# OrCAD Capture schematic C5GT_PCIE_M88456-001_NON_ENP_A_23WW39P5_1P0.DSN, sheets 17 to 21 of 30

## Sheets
17 10/100/1000 Ethernet PHY: size B
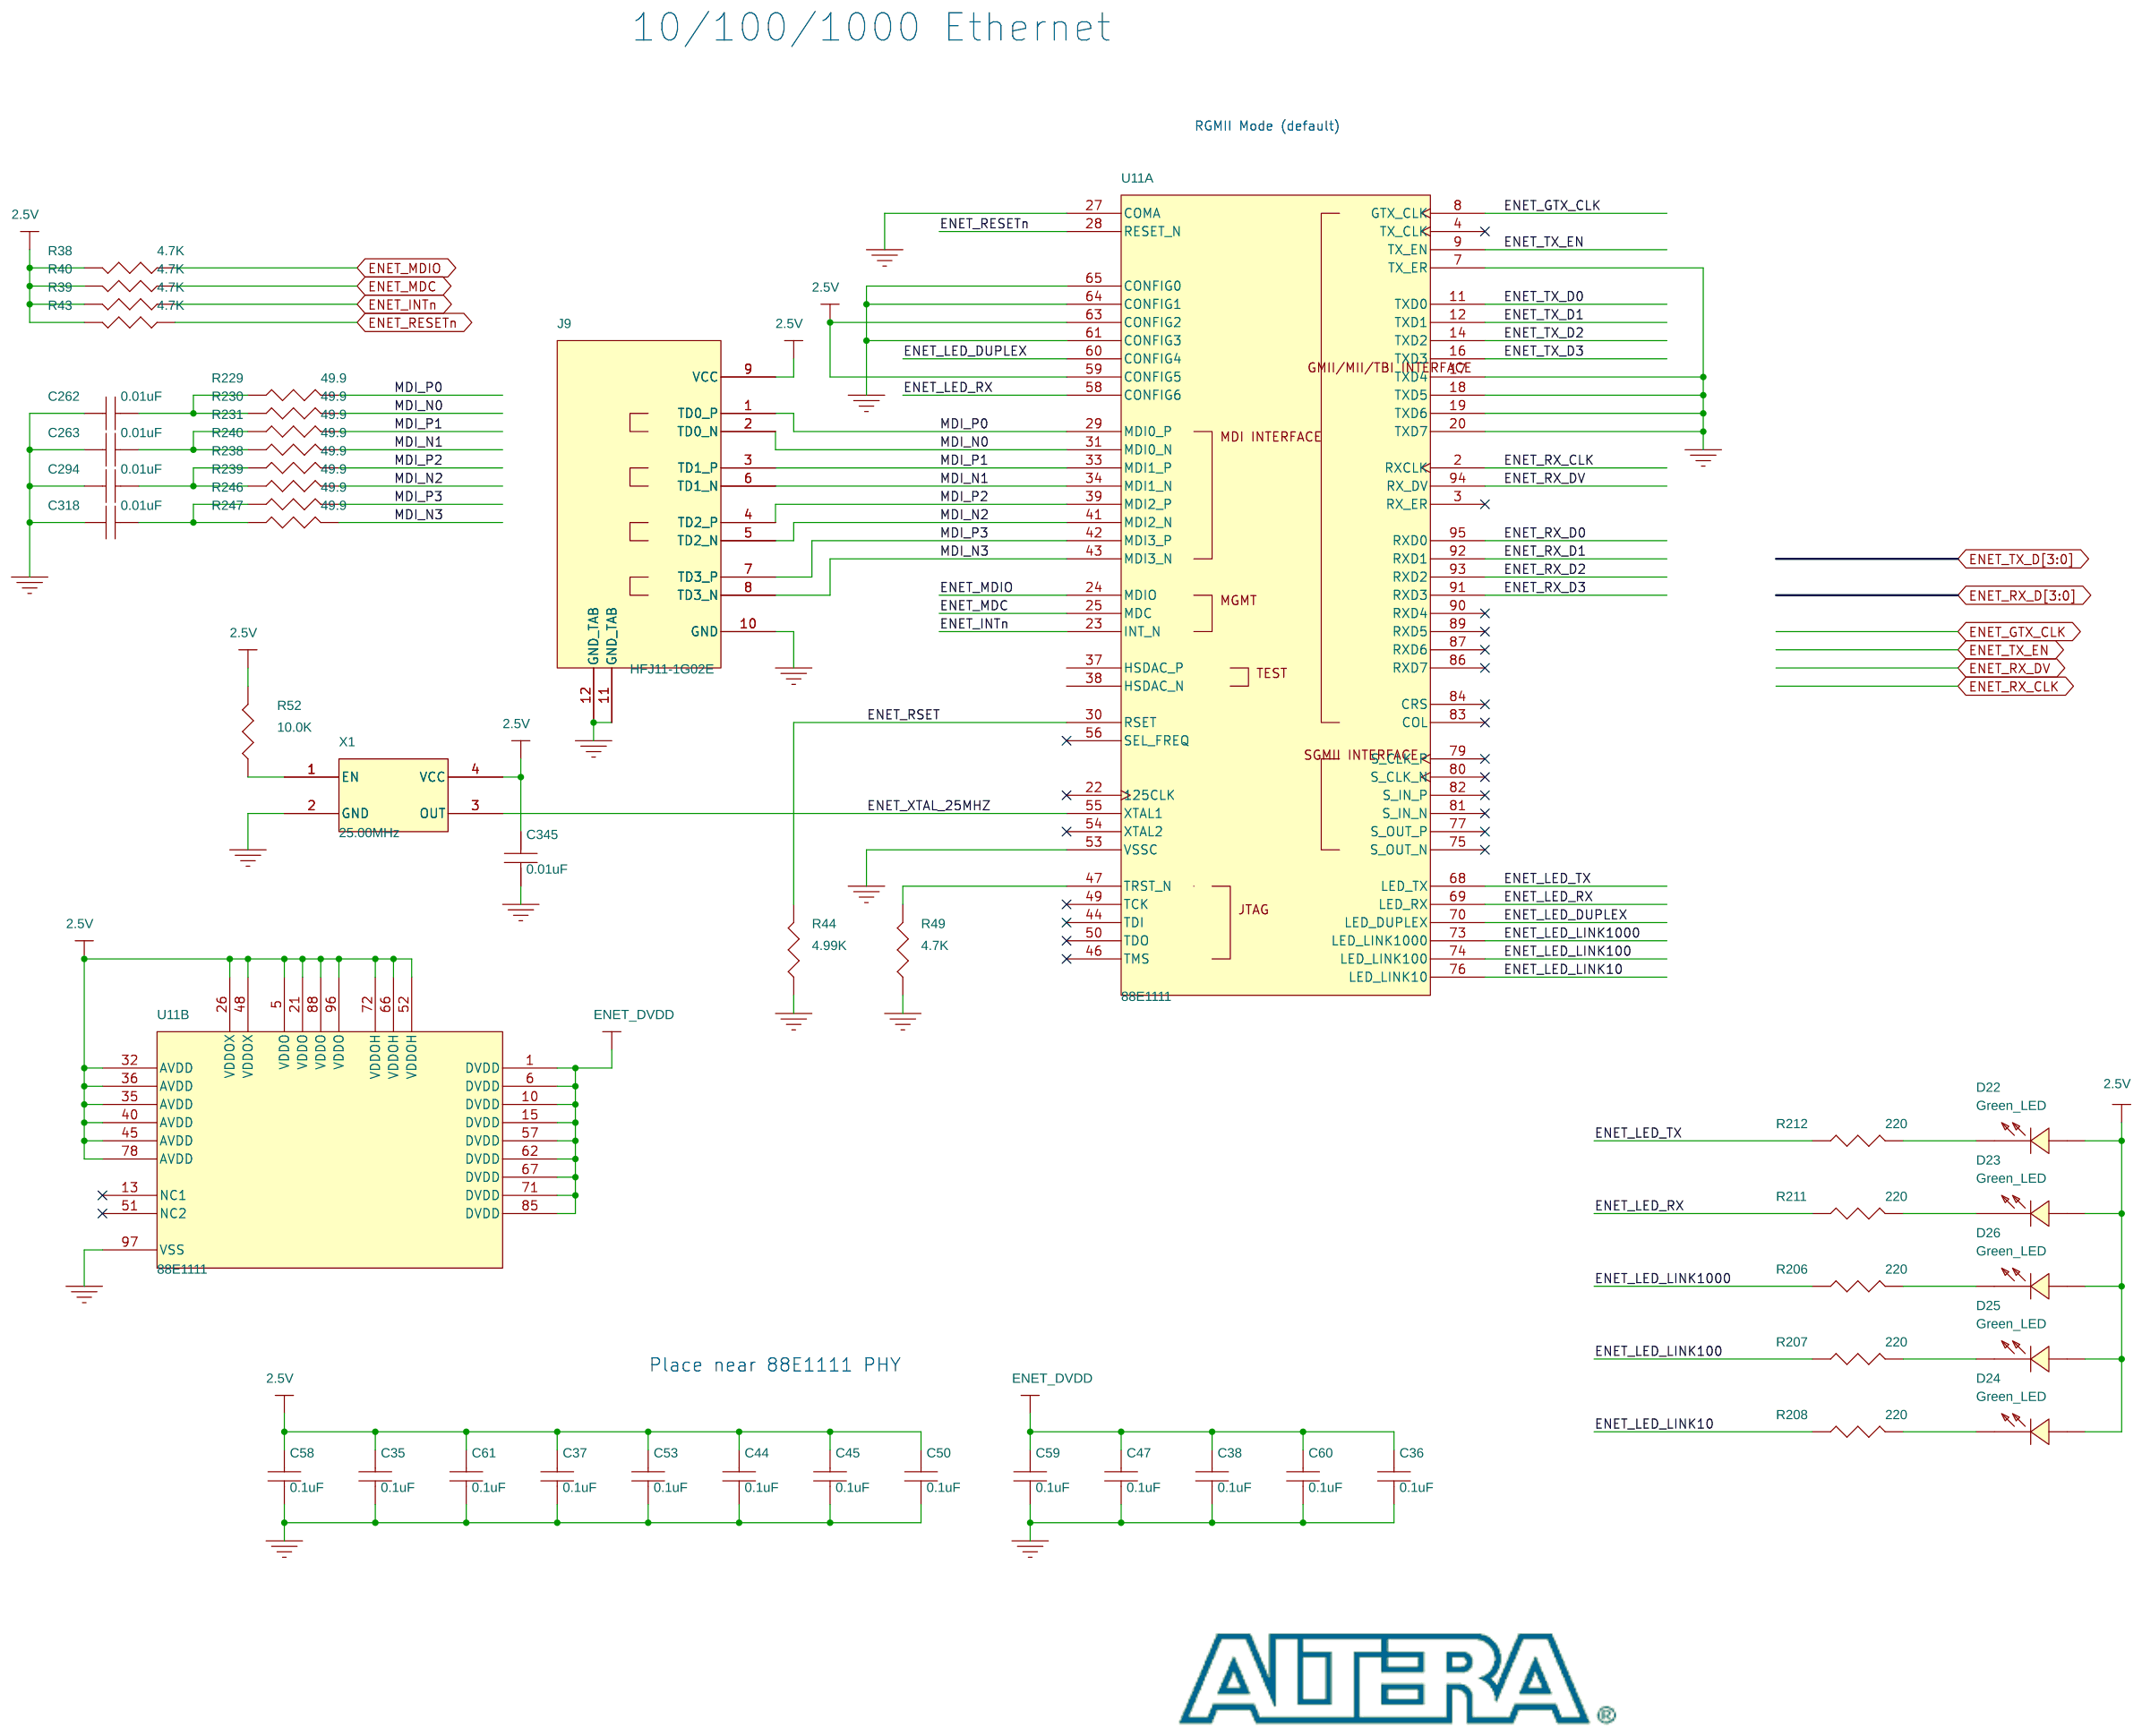
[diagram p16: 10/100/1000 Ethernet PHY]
18 HSMC Port A & Port B: size B
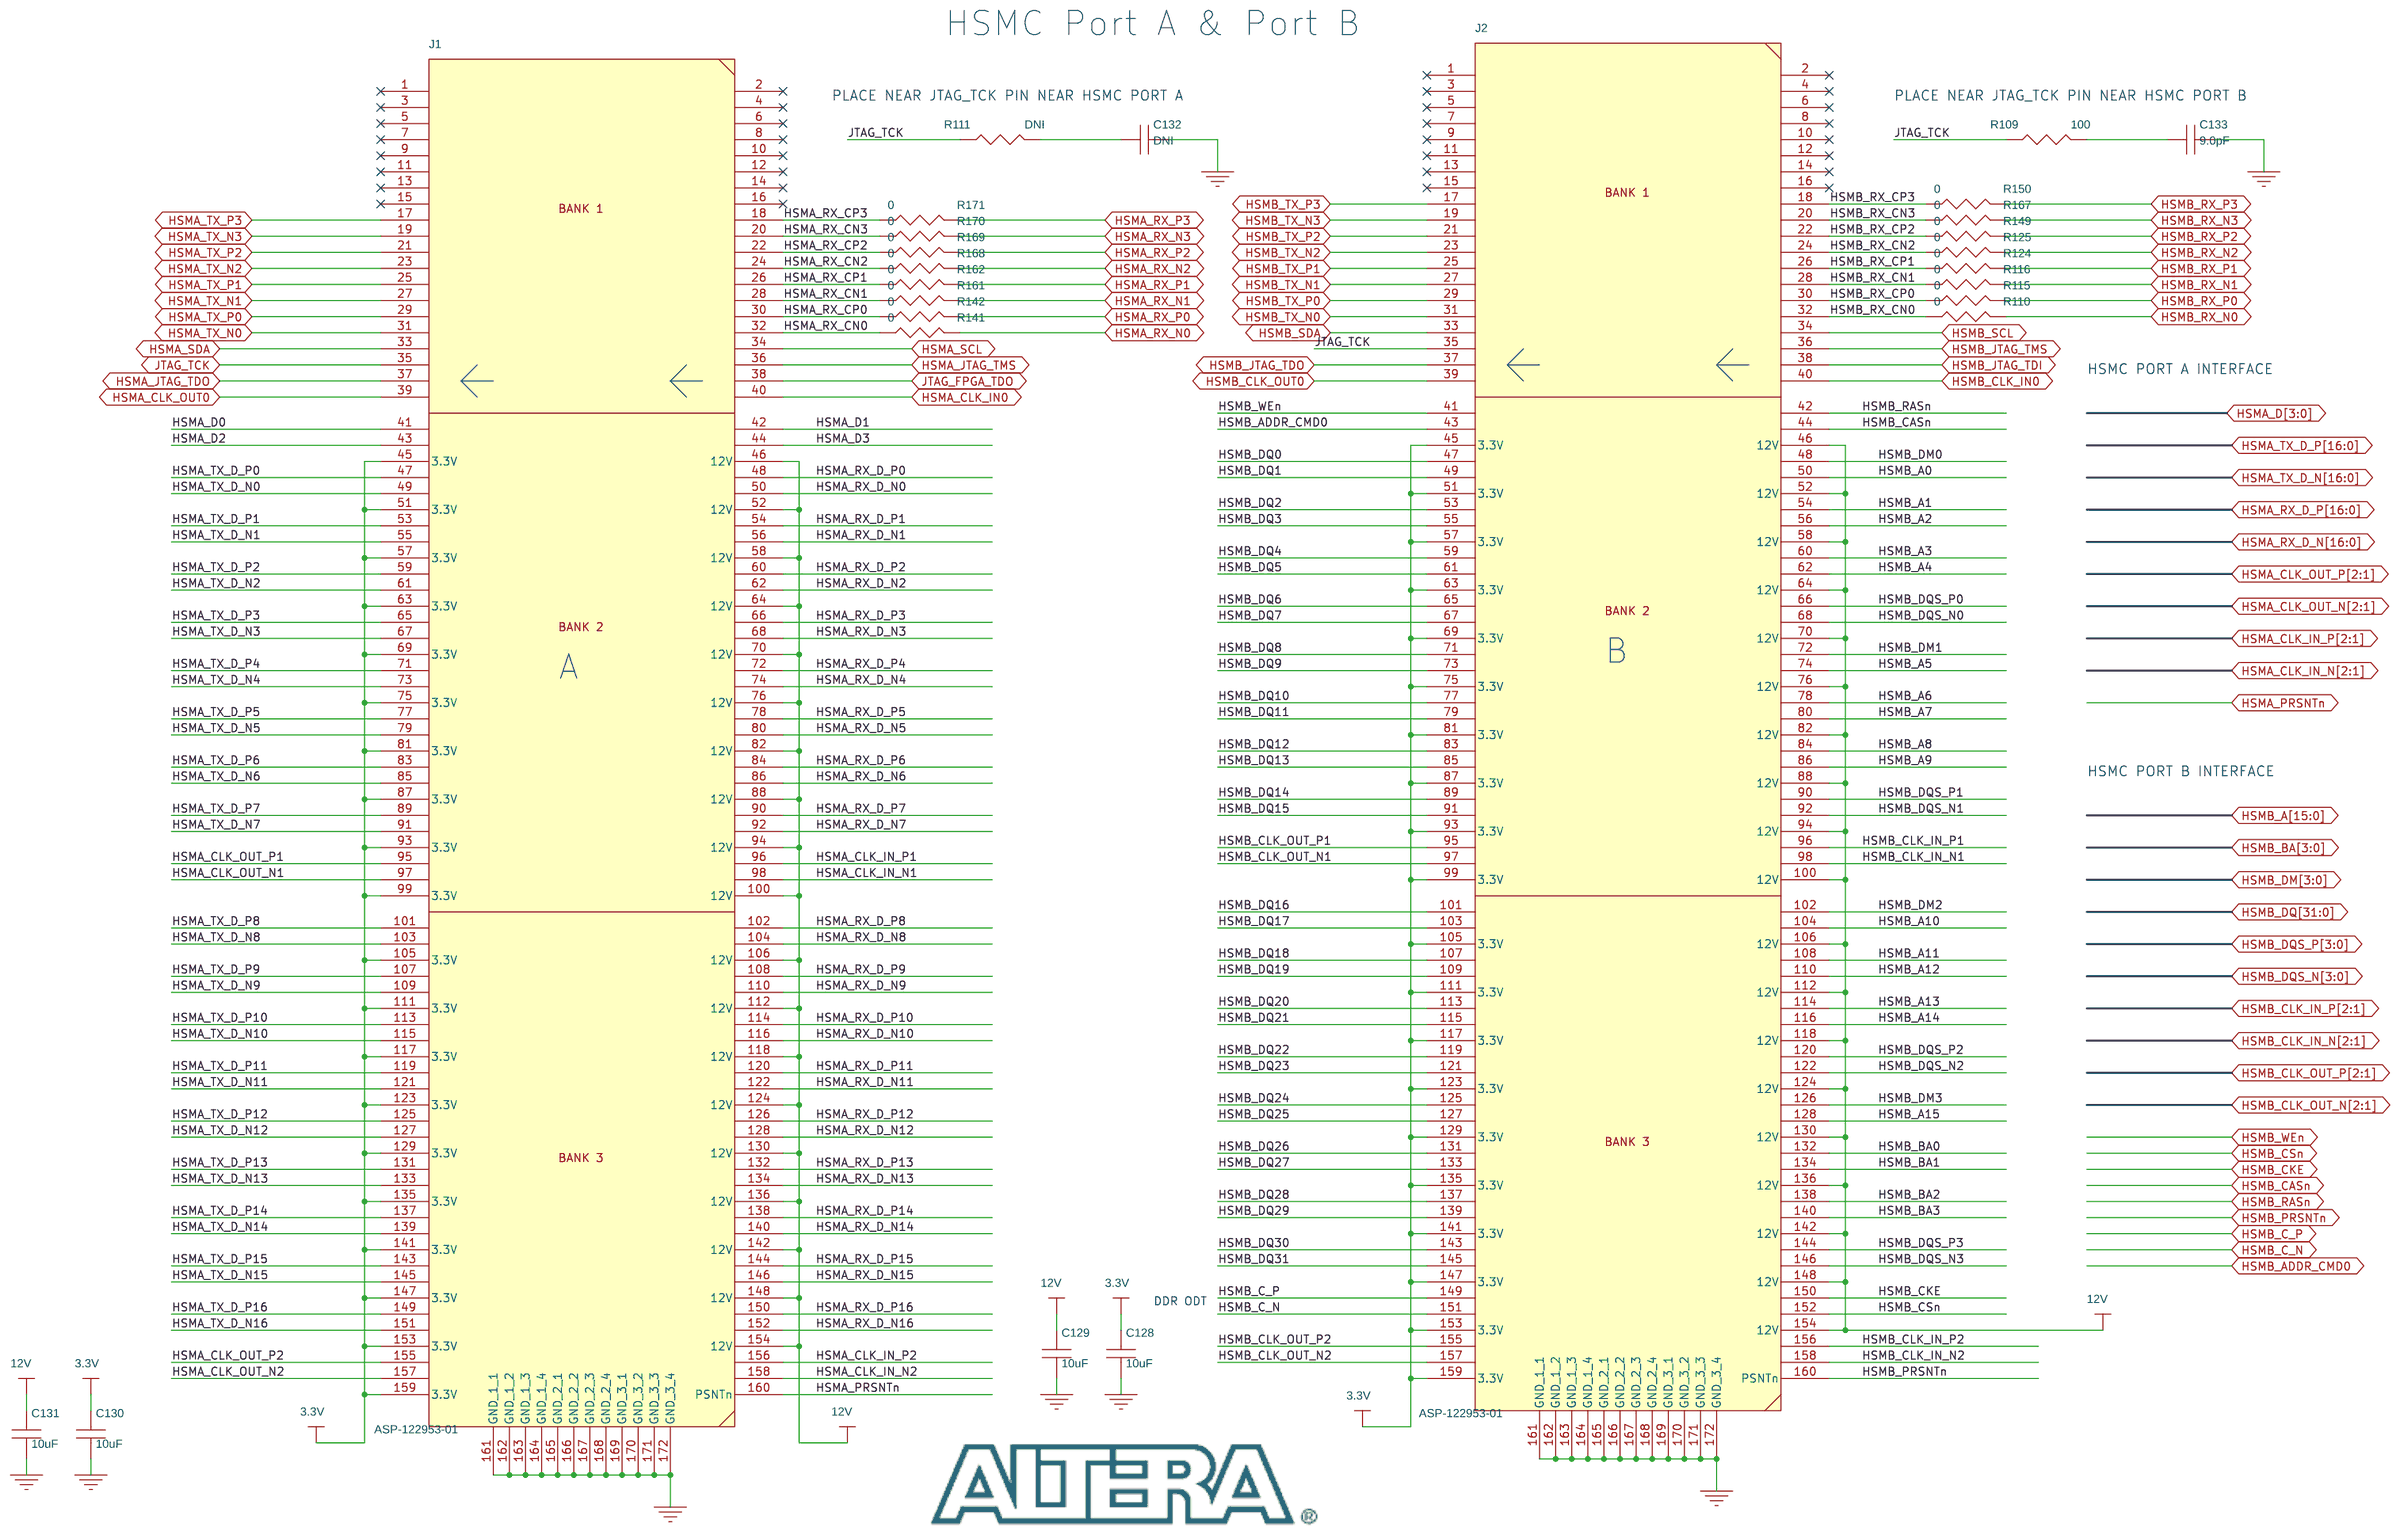
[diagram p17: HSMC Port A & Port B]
19 On-Board USB Blaster II: size B
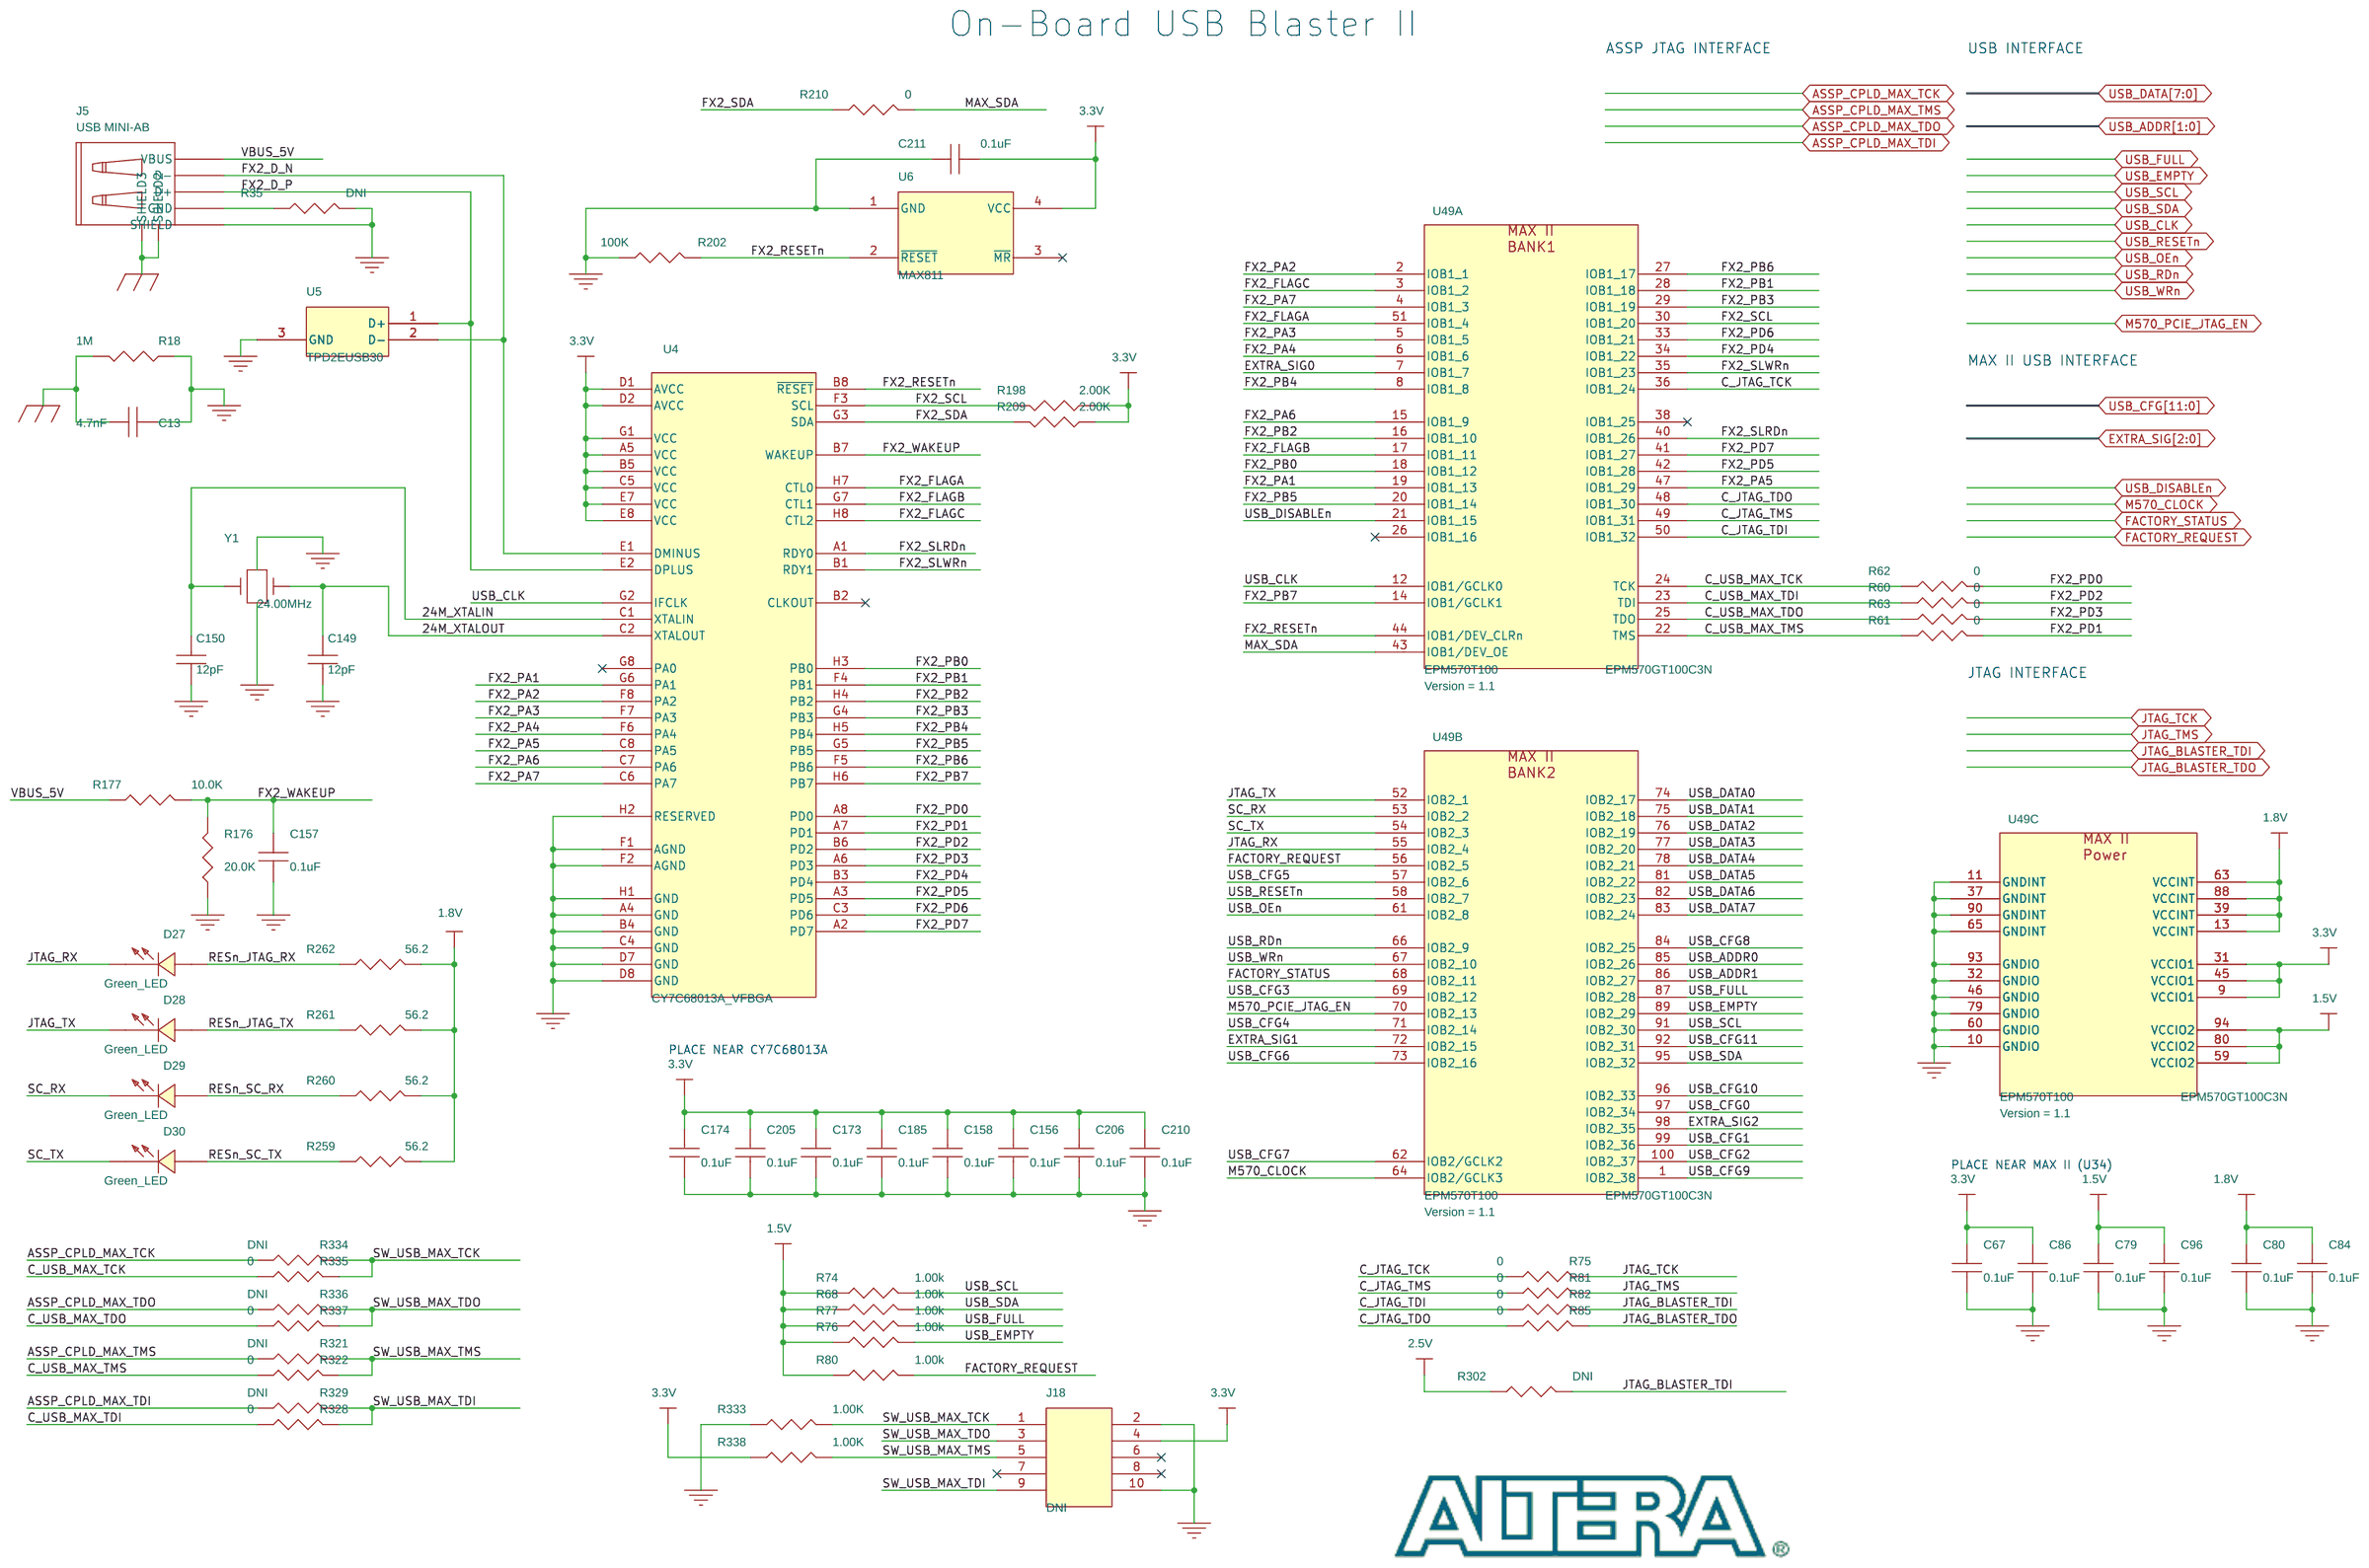
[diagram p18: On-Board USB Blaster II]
20 User IO: size B
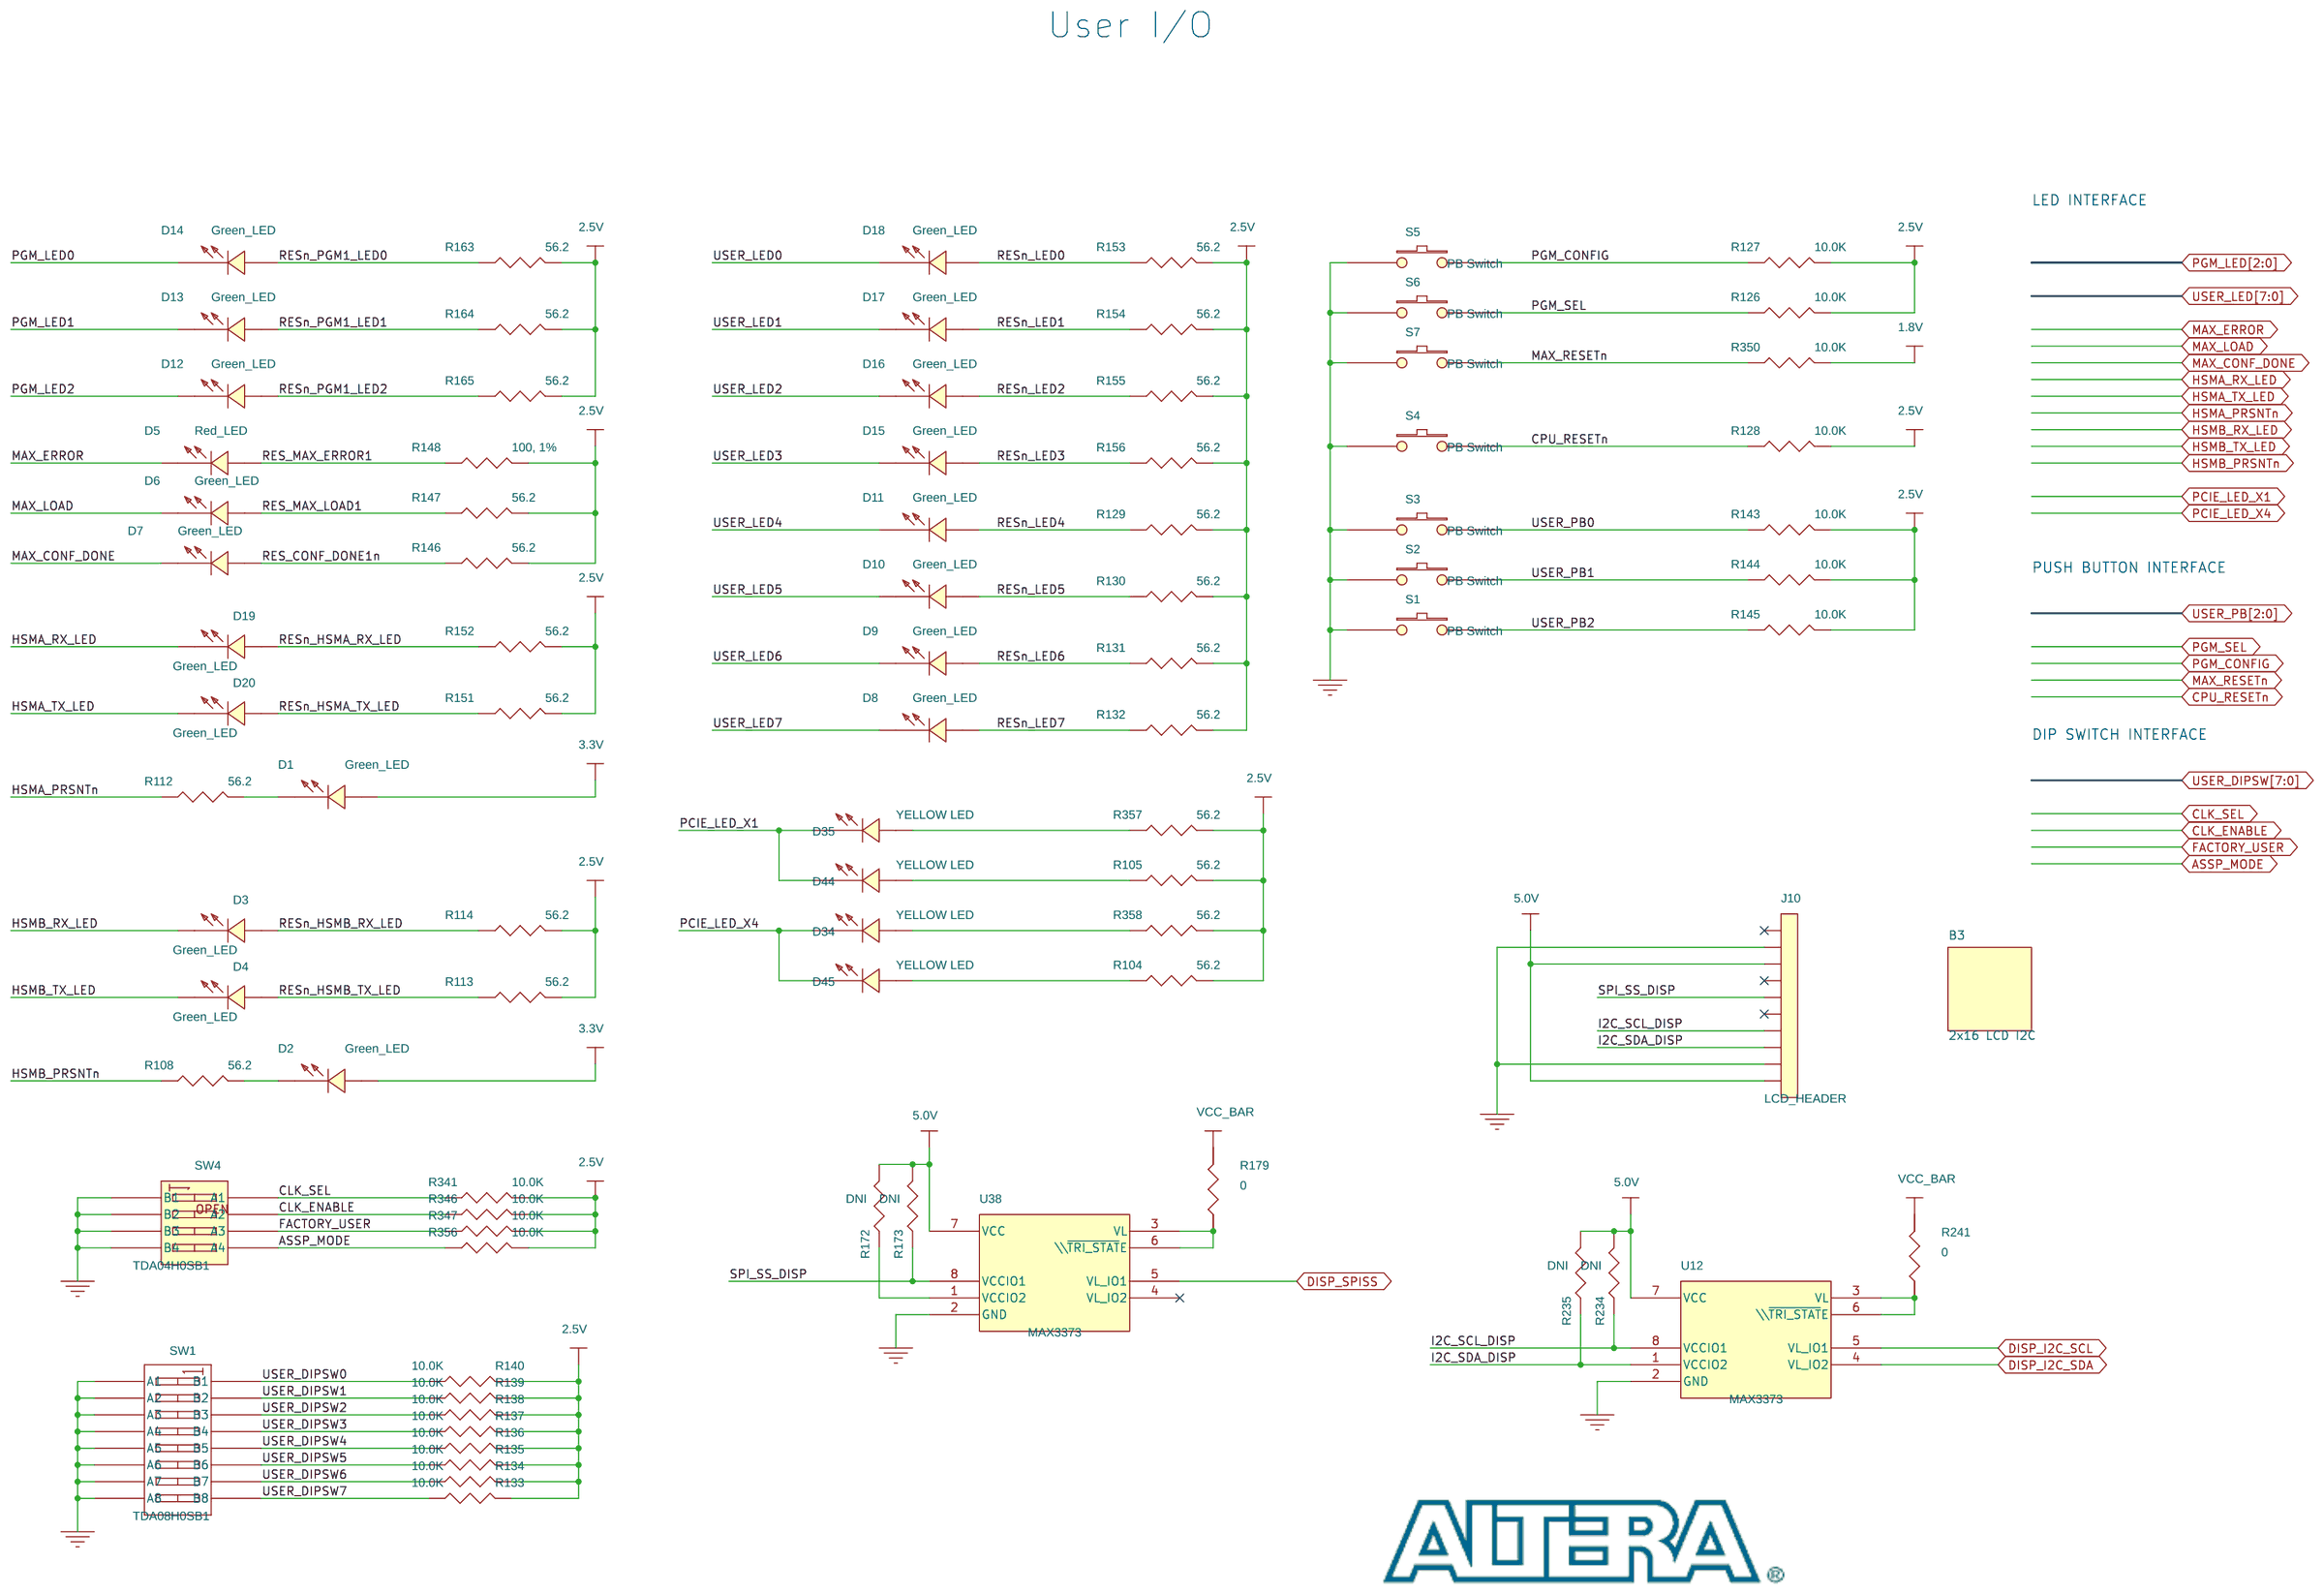
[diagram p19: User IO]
21 ASSP CPLD: size B
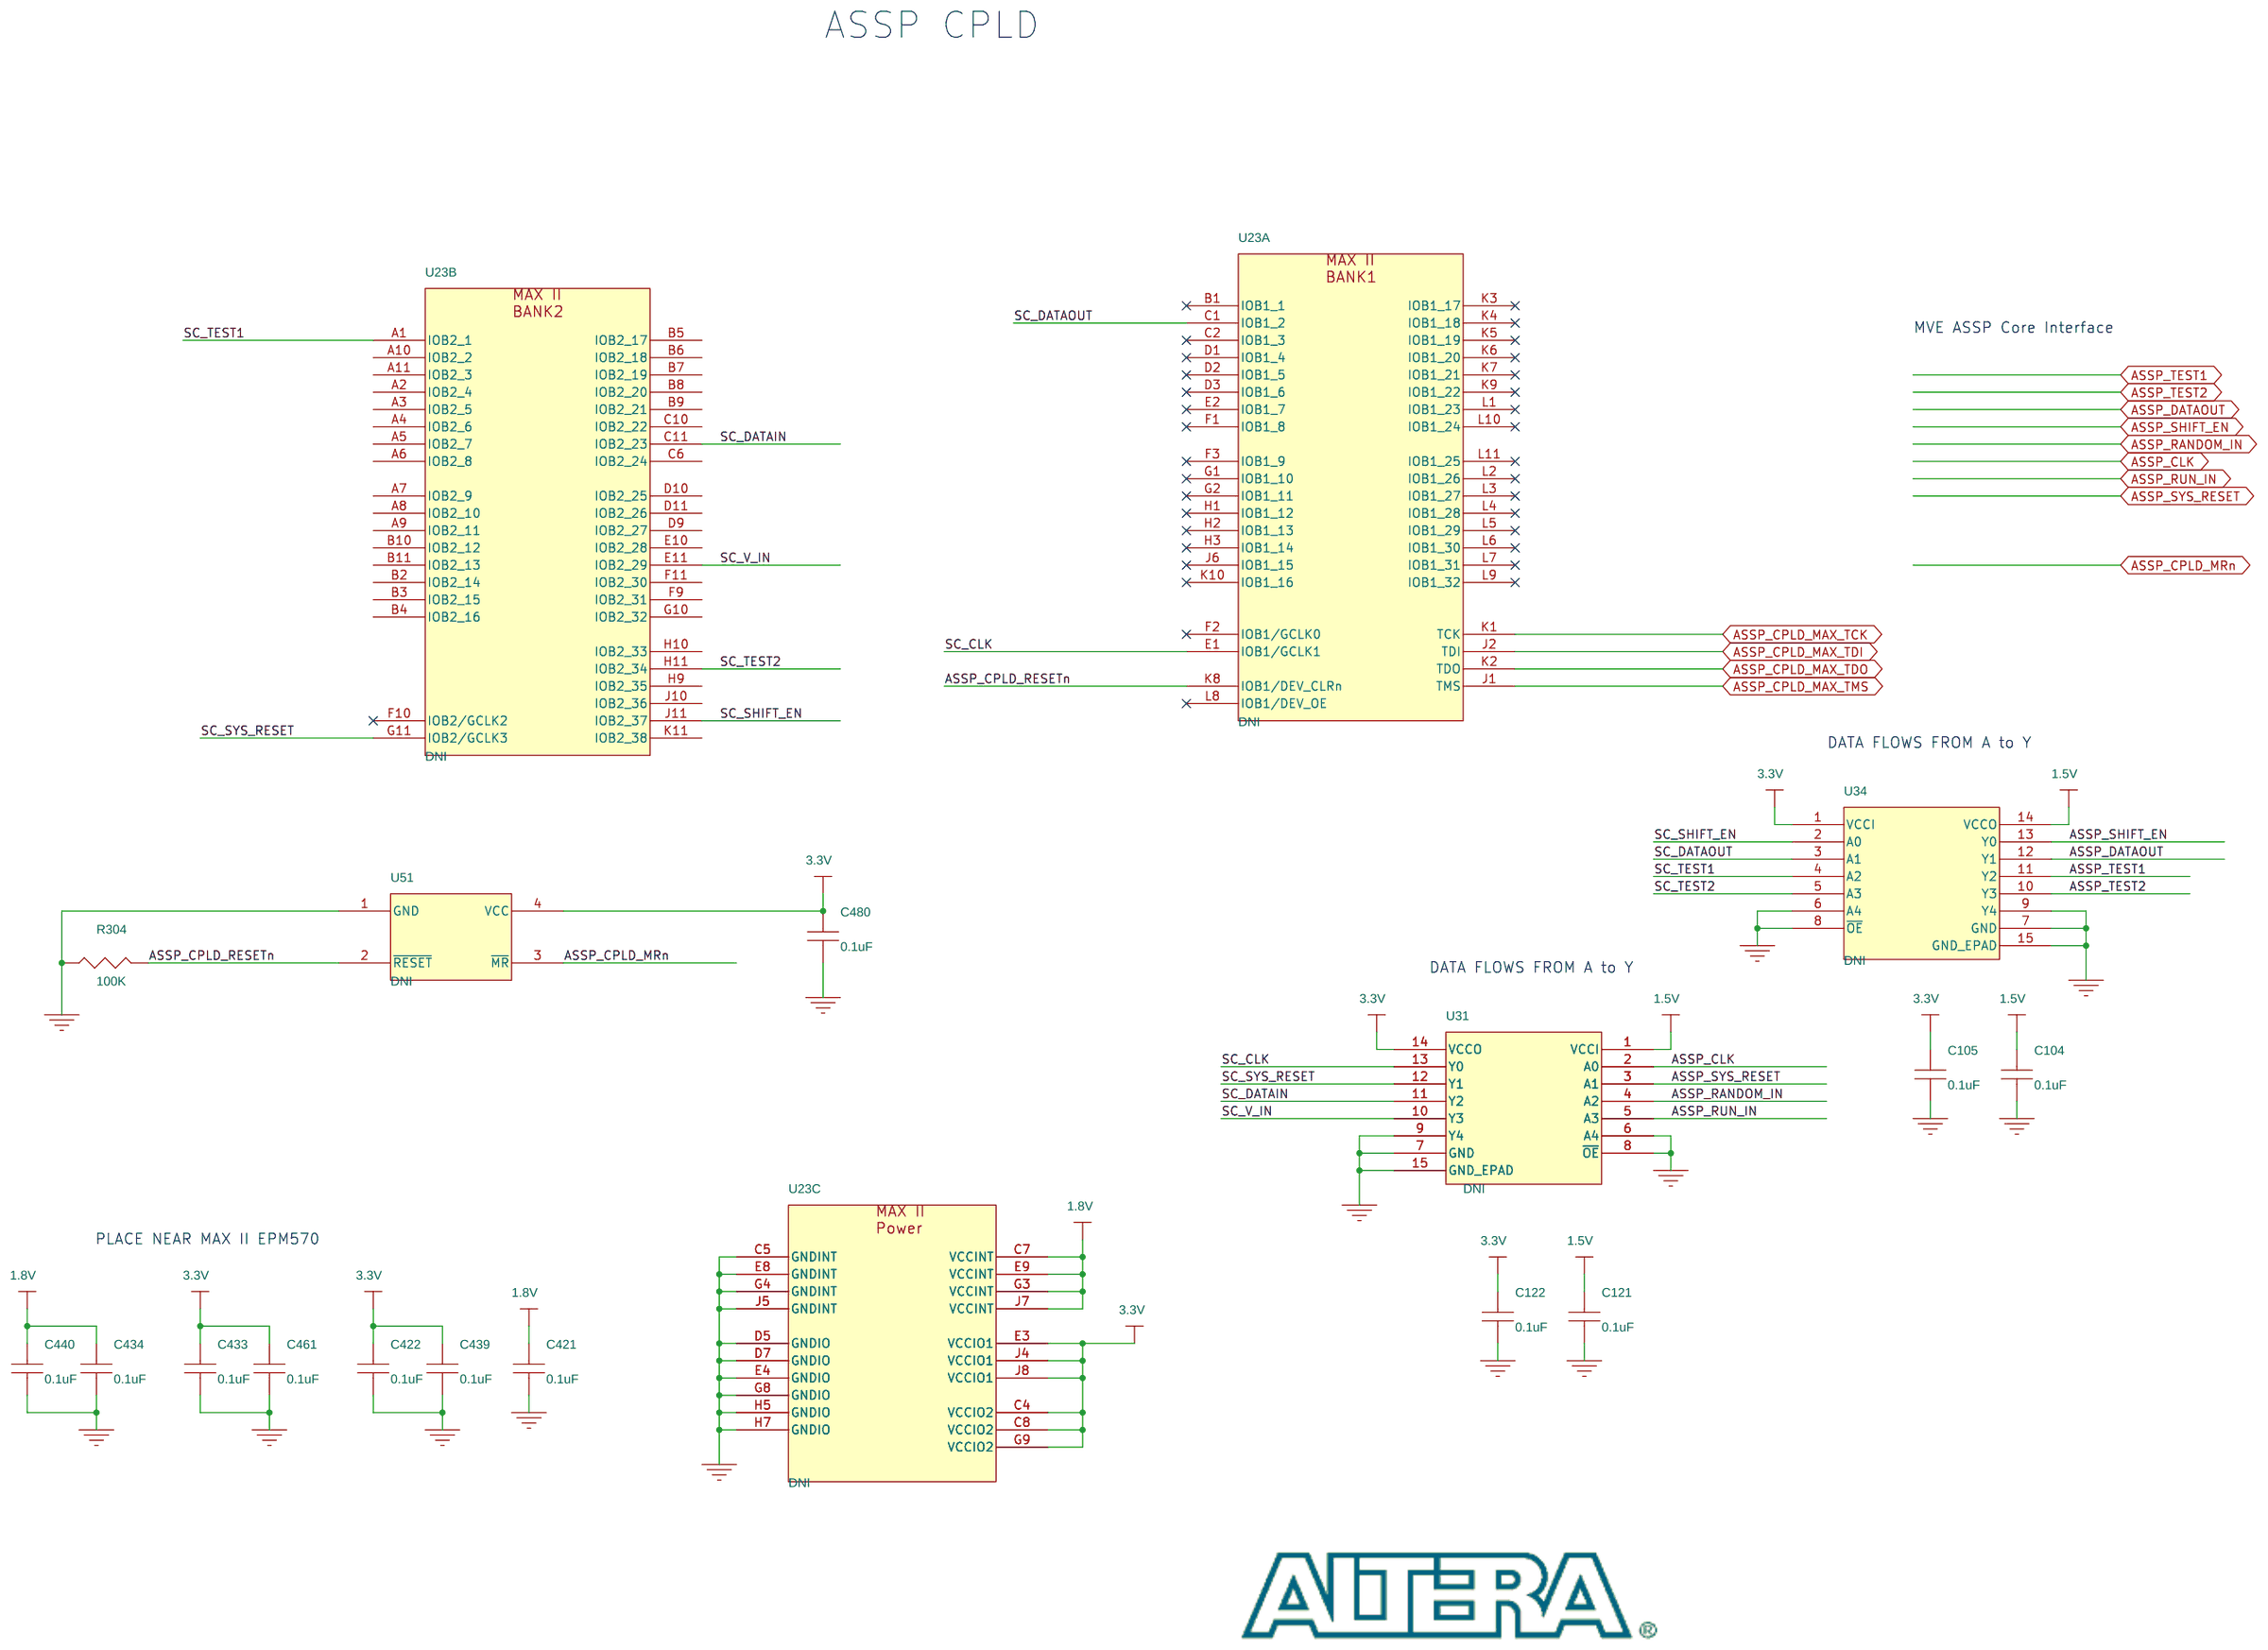
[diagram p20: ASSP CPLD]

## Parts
sheet 10/100/1000 Ethernet PHY
C35  0.1uF  [0402]
C36  0.1uF  [0402]
C37  0.1uF  [0402]
C38  0.1uF  [0402]
C44  0.1uF  [0402]
C45  0.1uF  [0402]
C47  0.1uF  [0402]
C50  0.1uF  [0402]
C53  0.1uF  [0402]
C58  0.1uF  [0402]
C59  0.1uF  [0402]
C60  0.1uF  [0402]
C61  0.1uF  [0402]
C262  0.01uF  [0402]
C263  0.01uF  [0402]
C294  0.01uF  [0402]
C318  0.01uF  [0402]
C345  0.01uF  [0402]
D22  Green_LED  [LUMEX_LED0805]
D23  Green_LED  [LUMEX_LED0805]
D24  Green_LED  [LUMEX_LED0805]
D25  Green_LED  [LUMEX_LED0805]
D26  Green_LED  [LUMEX_LED0805]
J9  HFJ11-1G02E  [rj45]
R38  4.7K  [0402]
R39  4.7K  [0402]
R40  4.7K  [0402]
R43  4.7K  [0402]
R44  4.99K  [0402]
R49  4.7K  [0402]
R52  10.0K  [0402]
R206  220  [0402]
R207  220  [0402]
R208  220  [0402]
R211  220  [0402]
R212  220  [0402]
R229  49.9  [0402]
R230  49.9  [0402]
R231  49.9  [0402]
R238  49.9  [0402]
R239  49.9  [0402]
R240  49.9  [0402]
R246  49.9  [0402]
R247  49.9  [0402]
U11  88E1111  [BCC96]  (sections A,B)
X1  25.00MHz  [XTAL_SG310]
sheet ASSP CPLD
C104  0.1uF  [0402]
C105  0.1uF  [0402]
C121  0.1uF  [0402]
C122  0.1uF  [0402]
C421  0.1uF  [0402]
C422  0.1uF  [0402]
C433  0.1uF  [0402]
C434  0.1uF  [0402]
C439  0.1uF  [0402]
C440  0.1uF  [0402]
C461  0.1uF  [0402]
C480  0.1uF  [0402]
R304  100K  [0402]
U23  DNI  [M100]  (sections A,B,C)
U31  DNI  [DQFN14]
U34  DNI  [DQFN14]
U51  DNI  [SOT-143]
sheet HSMC Port A & Port B
C128  10uF  [1206]
C129  10uF  [1206]
C130  10uF  [1206]
C131  10uF  [1206]
C132  DNI  [0402]
C133  9.0pF  [0402]
J1  ASP-122953-01  [SAMTEC_QSHDP120CUSTOM]
J2  ASP-122953-01  [SAMTEC_QSHDP120CUSTOM]
R109  100  [0402]
R110  0  [0402]
R111  DNI  [0402]
R115  0  [0402]
R116  0  [0402]
R124  0  [0402]
R125  0  [0402]
R141  0  [0402]
R142  0  [0402]
R149  0  [0402]
R150  0  [0402]
R161  0  [0402]
R162  0  [0402]
R167  0  [0402]
R168  0  [0402]
R169  0  [0402]
R170  0  [0402]
R171  0  [0402]
sheet On-Board USB Blaster II
C13  4.7nF  [0402]
C67  0.1uF  [0402]
C79  0.1uF  [0402]
C80  0.1uF  [0402]
C84  0.1uF  [0402]
C86  0.1uF  [0402]
C96  0.1uF  [0402]
C149  12pF  [0402]
C150  12pF  [0402]
C156  0.1uF  [0402]
C157  0.1uF  [0402]
C158  0.1uF  [0402]
C173  0.1uF  [0402]
C174  0.1uF  [0402]
C185  0.1uF  [0402]
C205  0.1uF  [0402]
C206  0.1uF  [0402]
C210  0.1uF  [0402]
C211  0.1uF  [0402]
D27  Green_LED  [LUMEX_LED0805]
D28  Green_LED  [LUMEX_LED0805]
D29  Green_LED  [LUMEX_LED0805]
D30  Green_LED  [LUMEX_LED0805]
J5  USB MINI-AB  [MOLEX_MINI-AB_USB_TH]
J18  DNI  [hdr2x5_100mil_smt]
R18  1M  [0402]
R35  DNI  [0402]
R60  0  [0402]
R61  0  [0402]
R62  0  [0402]
R63  0  [0402]
R68  1.00k  [0402]
R74  1.00k  [0402]
R75  0  [0402]
R76  1.00k  [0402]
R77  1.00k  [0402]
R80  1.00k  [0402]
R81  0  [0402]
R82  0  [0402]
R85  0  [0402]
R176  20.0K  [0402]
R177  10.0K  [0402]
R198  2.00K  [0402]
R202  100K  [0402]
R209  2.00K  [0402]
R210  0  [0402]
R259  56.2  [0402]
R260  56.2  [0402]
R261  56.2  [0402]
R262  56.2  [0402]
R302  DNI  [0402]
R321  DNI  [0402]
R322  0  [0402]
R328  0  [0402]
R329  DNI  [0402]
R333  1.00K  [0402]
R334  DNI  [0402]
R335  0  [0402]
R336  DNI  [0402]
R337  0  [0402]
R338  1.00K  [0402]
U4  CY7C68013A_VFBGA  [Vfbga56]
U5  TPD2EUSB30  [DRT]
U6  MAX811  [SOT-143]
U49  EPM570GT100C3N  [TQFP100SQ]  (sections A,B,C)
Y1  24.00MHz  [XTAL_FA-128]
sheet User IO
B3  2x16 LCD I2C  [newhaven_lcd]
D1  Green_LED  [LUMEX_LED0805]
D2  Green_LED  [LUMEX_LED0805]
D3  Green_LED  [LUMEX_LED0805]
D4  Green_LED  [LUMEX_LED0805]
D5  Red_LED  [LUMEX_LED0805]
D6  Green_LED  [LUMEX_LED0805]
D7  Green_LED  [LUMEX_LED0805]
D8  Green_LED  [LUMEX_LED0805]
D9  Green_LED  [LUMEX_LED0805]
D10  Green_LED  [LUMEX_LED0805]
D11  Green_LED  [LUMEX_LED0805]
D12  Green_LED  [LUMEX_LED0805]
D13  Green_LED  [LUMEX_LED0805]
D14  Green_LED  [LUMEX_LED0805]
D15  Green_LED  [LUMEX_LED0805]
D16  Green_LED  [LUMEX_LED0805]
D17  Green_LED  [LUMEX_LED0805]
D18  Green_LED  [LUMEX_LED0805]
D19  Green_LED  [LUMEX_LED0805]
D20  Green_LED  [LUMEX_LED0805]
D34  YELLOW LED  [LUMEX_LED0805]
D35  YELLOW LED  [LUMEX_LED0805]
D44  YELLOW LED  [LUMEX_LED0805]
D45  YELLOW LED  [LUMEX_LED0805]
J10  LCD_HEADER  [NEWHAVEN_LCD]
R104  56.2  [0402]
R105  56.2  [0402]
R108  56.2  [0402]
R112  56.2  [0402]
R113  56.2  [0402]
R114  56.2  [0402]
R126  10.0K  [0402]
R127  10.0K  [0402]
R128  10.0K  [0402]
R129  56.2  [0402]
R130  56.2  [0402]
R131  56.2  [0402]
R132  56.2  [0402]
R133  10.0K  [0402]
R134  10.0K  [0402]
R135  10.0K  [0402]
R136  10.0K  [0402]
R137  10.0K  [0402]
R138  10.0K  [0402]
R139  10.0K  [0402]
R140  10.0K  [0402]
R143  10.0K  [0402]
R144  10.0K  [0402]
R145  10.0K  [0402]
R146  56.2  [0402]
R147  56.2  [0402]
R148  100, 1%  [0402]
R151  56.2  [0402]
R152  56.2  [0402]
R153  56.2  [0402]
R154  56.2  [0402]
R155  56.2  [0402]
R156  56.2  [0402]
R163  56.2  [0402]
R164  56.2  [0402]
R165  56.2  [0402]
R172  DNI  [0402]
R173  DNI  [0402]
R179  0  [0402]
R234  DNI  [0402]
R235  DNI  [0402]
R241  0  [0402]
R341  10.0K  [0402]
R346  10.0K  [0402]
R347  10.0K  [0402]
R350  10.0K  [0402]
R356  10.0K  [0402]
R357  56.2  [0402]
R358  56.2  [0402]
S1  PB Switch  [WURTH_6X3P5_TACT_SWITCH]
S2  PB Switch  [WURTH_6X3P5_TACT_SWITCH]
S3  PB Switch  [WURTH_6X3P5_TACT_SWITCH]
S4  PB Switch  [WURTH_6X3P5_TACT_SWITCH]
S5  PB Switch  [WURTH_6X3P5_TACT_SWITCH]
S6  PB Switch  [WURTH_6X3P5_TACT_SWITCH]
S7  PB Switch  [WURTH_6X3P5_TACT_SWITCH]
SW1  TDA08H0SB1  [DIPSWITCH_SMT_OCTAL]
SW4  TDA04H0SB1  [DIPSWITCH_SMT_QUAD]
U12  MAX3373  [SOT23-8]
U38  MAX3373  [SOT23-8]

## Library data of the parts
C35-C38 C44 C45 C47 C50 C53 C58-C61 C67 C79 C80 C84 C86 C96 C156-C158 C173 C174 C185 C205 C206 C210 C211 = CAP: CAP - CERAMIC,  0.1UF 0402 25VDC Y5V; AGILE_LINK: http://sj-agile9app/Agile/PLMServlet?action=OpenEmailObject&classid=10000&objid=213459527; IPN: K13560-001; Item Num: P03-15057R; LIFECYCLE_PHASE: Active; Lead Free Status: Lead Free; MFR_LIFECYCLE: Active; Manufacturer: Murata; Manufacturer Part Num: GRM155F51E104ZA01D; Num Pins: 2; PART_SUBCLASS: CAPACITORS; Part Class: CAPACITORS; RATED_VOLTAGE: 25V; RoHS Compliant: RoHS Compliant; TOLERANCE: +80%/-20%
C262 C263 C294 C318 = CAP: CAP, CER .01UF 16V X7R 0402; IPN: A36096-007; Item Num: P03-15137R; Lead Free Status: No; Manufacturer: Murata; Manufacturer Part Num: GRM155R71C103KA01D; Manufacturer's Part No.: GRM155R71C103KA01D; Num Pins: 2; Part Class: CAPACITORS; Price: 0; RoHS Compliant: Yes
C345 = CAP: CAP,CER,0.01UF,0402,10%,25VD; IPN: A36096-045; Item Num: P03-11343R; Lead Free Status: No; Manufacturer: Panasonic; Manufacturer Part Num: ECJ-0EB1E103K; Num Pins: 2; Part Class: Capacitors; Price: 0; RoHS Compliant: Yes
D22-D26 = LED: LED - GREEN, VF=2.0V, 0805 SMD; Color Output: GREEN; IPN: E63507-001; Item Num: P09-21120R; Lead Free Status: No; Manufacturer: Lumex, Inc.; Manufacturer Part Num: SML-LXT0805GW-TR; Num Pins: 2; Part Class: LEDs; RoHS Compliant: Yes
J9 = HFJ11-1G02E: CONN RJ-45 SINGLE PORT 10/100/1000 BASET INTEGRATED MAGNETICS 10 PIN; IPN: K10883-001; Item Num: P23-35065R; Lead Free Status: No; Manufacturer: Halo Electronics, Inc.; Manufacturer Part Num: HFJ11-1G02ERL; Num Pins: 10; Part Class: Connectors; Price: 10; RoHS Compliant: Yes
R38-R40 R43 R49 = RESISTOR: RES 4.7K OHM 1/16W 5% 0402 SMD; IPN: A93549-020; Item Num: P02-14032R; Lead Free Status: No; Manufacturer: Panasonic; Manufacturer Part Num: ERJ-2GEJ472X; Manufacturer's Part No.: ERJ-2GEJ472X; Num Pins: 2; Part Class: Resistors; Price: 0; RoHS Compliant: Yes
R44 = RESISTOR: RES 4.99K OHM 1/16W 1% 0402 SMD; IPN: A78616-001; Item Num: P02-14129R; Lead Free Status: Yes; Manufacturer: Panasonic; Manufacturer Part Num: ERJ-2RKF4991X; Num Pins: 2; Part Class: Resistors; Price: 0
R52 R126-R128 R133-R140 R143-R145 R177 R341 R346 R347 R350 R356 = RESISTOR: RES,10.0K OHMS,1.0%,1/16W, 0402; AGILE_LINK: http://sj-agile9app/Agile/PLMServlet?action=OpenEmailObject&classid=10000&objid=146548997; IPN: A93548-034; Item Num: P02-11364R; LIFECYCLE_PHASE: Active; Lead Free Status: No; MFR_LIFECYCLE: Active; Manufacturer: Panasonic; Manufacturer Part Num: ERJ-2RKF1002X; Num Pins: 2; PART_SUBCLASS: RESISTORS; POWER: 1/16W; RESISTANCE: 10K; RoHS Compliant: Yes; TOLERANCE: +/-1%
R206-R208 R211 R212 = RESISTOR: RES, 220 OHMS, 5%, 1/16W, 0402; IPN: K15619-001; Item Num: P02-14107R; Lead Free Status: No; Manufacturer: Panasonic; Manufacturer Part Num: ERJ-2GEJ221X; Num Pins: 2; Part Class: Resistors; Price: 0
R229-R231 R238-R240 R246 R247 = RESISTOR: RES, 49.9 OHMS, 1%, 1/16W, 0402; IPN: K21587-001; Item Num: P02-14101R; Lead Free Status: Yes; Manufacturer: NIC Components Corp.; Manufacturer Part Num: NRC04F49R9TRF; Num Pins: 2; Part Class: Resistors; Price: 0
U11 = 88E1111: IC GIGE XCVR 10/100/1000BASE-T 2.5V 96-PIN BCC; IPN: G94223-001; Item Num: P01-13032R; Lead Free Status: Yes; Manufacturer: Marvell Semiconductor, Inc.; Manufacturer Part Num: 88E1111-B2-CAA1C000; Num Pins: 96; Part Class: ICs; Price: 0; RoHS Compliant: Yes
X1 = OSC_ALT: CRYSTAL, 25.000MHZ OSC, CMOS, 2.5V, SMT 3.2MM X 2.5MM, +/-50PPM; AGILE_LINK: http://sj-agile9app/Agile/PLMServlet?action=OpenEmailObject&classid=10000&objid=259526610; IPN: M94294-001; Item Num: P07-19194R; LIFECYCLE_PHASE: Preliminary; Lead Free Status: Lead Free; MFR_LIFECYCLE: Active; Manufacturer: Epson; Manufacturer Part Num: ECS-3225MVLC-250-CN-TR; Num Pins: 4; PART_SUBCLASS: CRYSTALS; RoHS Compliant: RoHS Compliant
C104 C105 C121 C122 C421 C422 C433 C434 C439 C440 C461 C480 = Cap_0.1UF_25VDC_0402: CAP - CERAMIC, 0.1UF 0402 25VDC Y5V; IPN: K13560-001; Manufacturer Part Num: GRM155F51E104ZA01D
R304 = RES_100K_OHM_1.0%_1_16W_0402: IPN: A93548-596
U23 = EPM570M100_0: IC - MAX II CPLD, 570 LEs, 100MBGA, 3.3/2.5V VCCINT; IPN: #N/A; Item Num: P01-17527R; Lead Free Status: Yes; Manufacturer: Altera Corporation; Manufacturer Part Num: EPM570M100C4N; Num Pins: 100; Part Class: ICs; RoHS Compliant: Yes
U31 U34 = FXL5T244: IPN: #N/A
U51 = RESET,_MAX811: IPN: D16587-001
C128-C131 = CAP: CAP, CERAMIC, 10uF, 10%, X5R, 25V, 1206; IPN: C71604-002; Item Num: P03-15063R; Manufacturer: Murata; Manufacturer Part Num: GRM31CR61E106KA12; Part Class: CAPACITORS
C132 C133 = CAP: CAP - CERAMIC,  9.0pF, +/- 0.5pF, 0402 50V, NPO; CAPACITANCE: 9.0 pF; IPN: A36094-075; Item Num: P03-17630R; LIFECYCLE_PHASE: Active; Lead Free Status: Lead Free; MFR_LIFECYCLE: Active; Manufacturer: Murata; Manufacturer Part Num: GRM1555C1H9R0BA01x; Num Pins: 2; PART_SUBCLASS: CAPACITORS; Part Class: CAPACITORS; RATED_VOLTAGE: 50V; RoHS Compliant: RoHS Compliant; TOLERANCE: +/-.05pF
J1 J2 = QSH_HSM: CONN - CUSTOM VERSION OF QSH-DP FAMILY HS SOCKET DIFF. PAIR 3 BANKS 172 PINS 0.5MM PITCH SMT; FPLIST: samtec_asp-122952-01,SAMTEC_QSHDP120CUSTOM; IPN: E81029-001; Item Num: P23-35087R; Lead Free Status: Yes; Manufacturer: Samtec; Num Pins: 172; Part Class: Connectors; Price: 5; RoHS Compliant: Yes
R109 R111 R148 = RESISTOR: RES,100 OHMS,1.0%,1/16W,0402; IPN: A36092-043; Item Num: P02-11381R; Lead Free Status: No; Manufacturer: Panasonic; Manufacturer Part Num: ERJ-2RKF1000X; Num Pins: 2; Part Class: RESISTORS; Price: 0; RoHS Compliant: Yes; Tolerance: 1%
R110 R115 R116 R124 R125 R141 R142 R149 R150 R161 R162 R167-R171 = RES_0_OHM_5%_1_16W_0402_SMD: IPN: A93549-001
C13 = CAP: CAP - CER 4700PF 50V 10% X7R 0402; AGILE_LINK: http://sj-agile9app/Agile/PLMServlet?action=OpenEmailObject&classid=10000&objid=215384813; IPN: A36096-066; Item Num: P03-15074R; LIFECYCLE_PHASE: Active; Lead Free Status: Lead Free; MFR_LIFECYCLE: Active; Manufacturer: Murata; Manufacturer Part Num: GRM155R71H472KA01D; Num Pins: 2; PACKAGING: Tape & Reel (TR); PART_SUBCLASS: CAPACITORS; RATED_VOLTAGE: 50V; RoHS Compliant: RoHS Compliant; Supplier Part Num: GRM155R71H472KA01D; Tolerance: +/-10%
C149 C150 = CAP: CAP - 12PF, 50V, +/-5%, CERAMIC, 0402 SMD; AGILE_LINK: http://sj-agile9app/Agile/PLMServlet?action=OpenEmailObject&classid=10000&objid=257385742; IPN: A36095-043; Item Num: P03-15352R; LIFECYCLE_PHASE: Active; Lead Free Status: Lead Free; MFR_LIFECYCLE: Active; Manufacturer: Panasonic; Manufacturer Part Num: ECJ-0EC1H120J; Num Pins: 2; PART_SUBCLASS: CAPACITORS; RATED_VOLTAGE: 50V; RoHS Compliant: RoHS Compliant; TOLERANCE: +/-5%
D27-D30 = LED: LED - GREEN, VF=2.0V, 0805 SMD; FPLIST: lumex_led1206,LED_1206; IPN: E63507-001; Item Num: P09-21120R; Lead Free Status: No; Manufacturer: Lumex, Inc.; Manufacturer Part Num: SML-LXT0805GW-TR; Num Pins: 2; Part Class: LEDs; Price: 0.07; RoHS Compliant: Yes
J5 = USB_CON_TH: CONN - MINI USB TYPE AB RECEPTICAL, 5POS, RT ANG PCB, TH; IPN: C56520-002; Item Num: P23-37753R; Lead Free Status: Lead Free; Manufacturer: Molex; Manufacturer Part Num: 56579-0519; Num Pins: 6; PART_SUBCLASS: Connectors; Part Class: Connectors; RoHS Compliant: Yes
J18 = 2x5: 2X5 .100" CENTER HEADER VERT SMD; IPN: #N/A; Item Num: P23-35059R; Lead Free Status: No; Manufacturer: Samtec; Manufacturer Part Num: TSM-105-01-T-DV-TR; Num Pins: 10; Part Class: Connectors; Price: 0; RoHS Compliant: Yes
R18 = RESISTOR: RES 1.00M OHM 1/16W 1% 0402 SMD; IPN: J15514-001; Item Num: P02-14034R; LIFECYCLE_PHASE: Active; Lead Free Status: Lead Free; MFR_LIFECYCLE: Active; Manufacturer: Panasonic; Manufacturer Part Num: ERJ-2RKF1004X; Num Pins: 2; Package: SMD; RoHS Compliant: RoHS Compliant; TOLERANCE: +/-1%
R35 R321 R329 R334 R336 = RESISTOR: RES ZERO OHM 1/16W 5% 0402 SMD; Altera Part No.: P02-14020R; IPN: A93549-001; Item Num: P02-14020R; Lead Free Status: No; Manufacturer: Panasonic; Manufacturer Part Num: ERJ-2GE0R00X; Num Pins: 2; Part Class: RESISTORS; Price: 0; RoHS Compliant: Yes; Tolerance: 5%
R60-R63 R75 R81 R82 R85 R210 R322 R328 R335 R337 = RESISTOR: RES ZERO OHM 1/16W 5% 0402 SMD; Altera Part No.: P02-14020R; IPN: A93549-001; Item Num: P02-14020R; Lead Free Status: No; Manufacturer: Panasonic; Manufacturer Part Num: ERJ-2GE0R00X; Num Pins: 2; Part Class: RESISTORS; RoHS Compliant: Yes; Tolerance: 5%
R68 R74 R76 R77 R80 R302 = RESISTOR: RES,1.00K OHMS,1.0%,1/16W,0402; IPN: G60609-021; Item Num: P02-11372R; Lead Free Status: No; Manufacturer: Panasonic; Manufacturer Part Num: ERJ-2RKF1001X; Num Pins: 2; Part Class: Resistors
R176 = RESISTOR: RES 20.0K OHM 1/16W 1% 0402 SMD; IPN: A93548-181; Item Num: P02-14071R; Lead Free Status: Yes; Manufacturer: Panasonic; Manufacturer Part Num: ERJ-2RKF2002X; Num Pins: 2; Part Class: RESISTORS; RoHS Compliant: Yes
R198 R209 = RESISTOR: RES,2.00K OHMS,1.0%,1/16W,0402; IPN: A93548-138; Item Num: P02-11376R; Lead Free Status: No; Manufacturer: Panasonic; Manufacturer Part Num: ERJ-2RKF2001X; Manufacturer's Part No.: ERJ-2RKF2001X; Num Pins: 2; Part Class: RESISTORS; Price: 0; RoHS Compliant: Yes
R202 = RESISTOR: RES,100K OHMS,1.0%,1/16W,0402; IPN: A93548-596; Item Num: P02-11386R; Lead Free Status: No; Manufacturer: Panasonic; Manufacturer Part Num: ERJ-2RKF1003X; Num Pins: 2; Part Class: Resistors; Price: 0; RoHS Compliant: Yes
R104 R105 R108 R112-R114 R129-R132 R146 R147 R151-R156 R163-R165 R259-R262 R357 R358 = RESISTOR: RES,56.2 OHMS,1.0%,1/16W,0402; IPN: K21576-001; Item Num: P02-11370R; Lead Free Status: No; Manufacturer: Panasonic; Manufacturer Part Num: ERJ-2RKF56R2X; Manufacturer's Part No.: ERJ-2RKF56R2X; Num Pins: 2; Part Class: RESISTORS; Price: 0; RoHS Compliant: Yes
R333 R338 = RESISTOR: RES,1.00K OHMS,1.0%,1/16W,0402; IPN: G60609-021; Item Num: P02-11372R; Lead Free Status: No; Manufacturer: Panasonic; Manufacturer Part Num: ERJ-2RKF1001X; Num Pins: 2; Part Class: Resistors; Price: 0
U4 = CY7C68013A_VFBGA: IC - EZ-USB FX2LP Microcontroller 400KHz, 56-VFBGA, 3.3V; IPN: J41178-001; Item Num: P01-17506R; Lead Free Status: Yes; Manufacturer: Cypress; Manufacturer Part Num: CY7C68013A-56BAXC; Num Pins: 56; Part Class: ICs; RoHS Compliant: Yes
U5 = TPD2EUSB30: DIODE - FULL SPEED USB ESD SOLUTION, 2CH, SOT3; IPN: K12736-001; Item Num: P08-20777R; Lead Free Status: Yes; MFR_LIFECYCLE: Active; Manufacturer: Texas Instruments; Manufacturer Part Num: TPD2EUSB30DRxx; Num Pins: 3; Part Class: ICS; RoHS Compliant: Yes
U6 = MAX811: IC - MPU V-MONITOR 2.93V, RESET/POWER-ON RESET, SOT143-4; IPN: D16587-001; Item Num: P01-17588R; Lead Free Status: Yes; Manufacturer: Maxim Integrated Products; Manufacturer Part Num: MAX811SEUS+T; Num Pins: 4; Part Class: ICs; RoHS Compliant: Yes
U49 = EPM570T100: IC - MAX II CPLD 570LE 16MMX16MM, TQFP 100-PIN; IPN: 971403; Item Num: P01-13171R; Manufacturer: Altera Corporation; Version: 1.1
Y1 = CRYSTAL_SM_13: CRYSTAL - MINI XTL, 24.00 MHZ, +/-50PPM, +/-30PPM-20~75C, 12PF, 2.0mm x 1.6mm SMD; IPN: K15535-001; Item Num: P07-19648R; Lead Free Status: Yes; MFR_LIFECYCLE: Active; Manufacturer: Epson Toyocom; Manufacturer Part Num: FA-128 24.0000MB-W:; Num Pins: 4; RoHS Compliant: Yes
B3 = BLANK_PART: LCD - 2X16 CHARACTER DISPLAY, I2C / SPI / RS232, 5.0V, BLUE WITH WHITE CHAR; IPN: K15374-001; Item Num: P10-22185R; Manufacturer: Newhaven; Manufacturer Part Num: NHD-0216K3Z-NSW-BBW-V3; Manufacturer's Part No.: NHD-0216K3Z-NSW-BBW-V3
D1-D4 D6-D20 = LED: LED - GREEN, VF=2.0V, 0805 SMD; IPN: E63507-001; Item Num: P09-21120R; Lead Free Status: No; Manufacturer: Lumex, Inc.; Manufacturer Part Num: SML-LXT0805GW-TR; Num Pins: 2; Part Class: LEDs; RoHS Compliant: Yes
D5 = LED: LED - RED, VF=2.0V, 0805 SMD; IPN: K15339-001; Item Num: P09-21200R; Lead Free Status: No; Manufacturer: Lumex, Inc.; Manufacturer Part Num: SML-LXT0805IW-TR; Num Pins: 2; Part Class: LEDs; Price: 0.07; RoHS Compliant: Yes
D34 D35 D44 D45 = LED: LED - YELLOW, VF=2.1V, 0805 SMD; IPN: H36732-001; Item Num: P09-21320R; LIFECYCLE_PHASE: Active; Lead Free Status: Lead Free; Manufacturer: Lumex, Inc.; Manufacturer Part Num: SML-LXT0805YW-TR; Num Pins: 2; PART_SUBCLASS: LEDS; Part Class: LEDS; RoHS Compliant: RoHS Compliant
J10 = LCD_HEADER: IPN: J42925-001; Item Num: P23-38501R; Lead Free Status: YES; Manufacturer Part Num: SSW-110-01-G-S; Num Pins: 10; Part Class: CONN
R172 R173 R234 R235 = RESISTOR: RES 10K OHM 1/16W 5% 0402 SMD; IPN: D83138-001; Item Num: P02-14023R; Lead Free Status: No; Manufacturer: Panasonic; Manufacturer Part Num: ERJ-2GEJ103X; Manufacturer's Part No.: ERJ-2GEJ103X; Num Pins: 2; Part Class: RESISTORS; Price: 0; RoHS Compliant: Yes
R179 R241 = RESISTOR: RES ZERO OHM 1/16W 5% 0402 SMD; Altera Part No.: P02-14020R; IPN: A93549-001; Item Num: P02-14020R; LIFECYCLE_PHASE: Active; Lead Free Status: No; MFR_LIFECYCLE: Active; Manufacturer: Panasonic; Manufacturer Part Num: ERJ-2GE0R00X; Num Pins: 2; PART_SUBCLASS: RESISTORS; POWER: 1/16W; Part Class: RESISTORS; RoHS Compliant: RoHS Compliant; Tolerance: +/-5%
S1-S7 = TS-A02SA-2-S100_0: SWITCH - PUSH BUTTON 6.0X3.5MM SND; IPN: K11478-001; Item Num: P23-38485R; Lead Free Status: Yes; Manufacturer: Wurth Elektroniks; Manufacturer Part Num: 434121043816; Num Pins: 2; Part Class: Switches; RoHS Compliant: Yes
SW1 = 76SB08: SWITCH, 8 POS, 16 PIN, DIP, SMT; IPN: A62367-002; Item Num: P11-24005R; Manufacturer: C&K Components/ITT Industries
SW4 = SPST4: SWITCHES - 4 POS, 8 PIN, Ultra-mini SMT Half-pitch Slider DIP Switch; AGILE_LINK: http://sj-agile9app/Agile/PLMServlet?action=OpenEmailObject&classid=10000&objid=258073635; IPN: A35353-010; Item Num: P11-24098R; LIFECYCLE_PHASE: Preliminary; Lead Free Status: Not Lead Free; MFR_LIFECYCLE: Active; Manufacturer: C & K Components/ITT Industries; Num Pins: 8; PART_SUBCLASS: SWITCHES; RoHS Compliant: RoHS Compliant
U12 U38 = MAX3372EEKA_0: IC - ±15KV ESD-PROTECTED, 1?A, 16MBPS, DUAL/QUAD LOW-VOLTAGE LEVEL TRANSLATORS IN UCSP; IPN: D26728-001; Item Num: P01-13324R; Lead Free Status: Yes; Manufacturer: Maxim Integrated Products, Inc.; Manufacturer Part Num: MAX3373EEKA+T; Num Pins: 8; Part Class: ICs; Price: 0

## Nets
1.5V: C79.1 C96.1 C104.1 C121.1 R68.1 R74.1 R76.1 R77.1 R80.1 U31.1(VCCI) U34.14(VCCO) U49.59(VCCIO2) U49.80(VCCIO2) U49.94(VCCIO2) ; also on sheet 27
1.8V: C80.1 C84.1 C421.1 C434.1 C440.1 R259.2 R260.2 R261.2 R262.2 R350.2 U23.C7(VCCINT) U23.E9(VCCINT) U23.G3(VCCINT) U23.J7(VCCINT) U49.13(VCCINT) U49.39(VCCINT) U49.63(VCCINT) U49.88(VCCINT) ; also on sheet 8 14 15 26 29
2.5V: C35.1 C37.1 C44.1 C45.1 C50.1 C53.1 C58.1 C61.1 C345.1 D22.1(ANODE) D23.1(ANODE) D24.1(ANODE) D25.1(ANODE) D26.1(ANODE) J9.9(VCC) R38.2 R39.2 R40.2 R43.2 R52.2 R104.2 R105.2 R113.2 R114.2 R126.2 R127.2 R128.2 R129.2 R130.2 R131.2 R132.2 R133.2 R134.2 R135.2 R136.2 R137.2 R138.2 R139.2 R140.2 R143.2 R144.2 R145.2 R146.2 R147.2 R148.2 R151.2 R152.2 R153.2 R154.2 R155.2 R156.2 R163.2 R164.2 R165.2 R179.2 R241.2 R302.1 R341.2 R346.2 R347.2 R356.2 R357.2 R358.2 U11.5(VDDO) U11.21(VDDO) U11.26(VDDOX) U11.32(AVDD) U11.35(AVDD) U11.36(AVDD) U11.40(AVDD) U11.45(AVDD) U11.48(VDDOX) U11.52(VDDOH) U11.59(CONFIG5) U11.63(CONFIG2) U11.66(VDDOH) U11.72(VDDOH) U11.78(AVDD) U11.88(VDDO) U11.96(VDDO) X1.4(VCC) ; also on sheet 3 8 10 11 15 22 26 29
3.3V: C67.1 C86.1 C105.1 C122.1 C128.1 C130.1 C156.1 C158.1 C173.1 C174.1 C185.1 C205.1 C206.1 C210.1 C211.2 C422.1 C433.1 C439.1 C461.1 C480.1 D1.1(ANODE) D2.1(ANODE) J1.45(3.3V) J1.51(3.3V) J1.57(3.3V) J1.63(3.3V) J1.69(3.3V) J1.75(3.3V) J1.81(3.3V) J1.87(3.3V) J1.93(3.3V) J1.99(3.3V) J1.105(3.3V) J1.111(3.3V) J1.117(3.3V) J1.123(3.3V) J1.129(3.3V) J1.135(3.3V) J1.141(3.3V) J1.147(3.3V) J1.153(3.3V) J1.159(3.3V) J2.45(3.3V) J2.51(3.3V) J2.57(3.3V) J2.63(3.3V) J2.69(3.3V) J2.75(3.3V) J2.81(3.3V) J2.87(3.3V) J2.93(3.3V) J2.99(3.3V) J2.105(3.3V) J2.111(3.3V) J2.117(3.3V) J2.123(3.3V) J2.129(3.3V) J2.135(3.3V) J2.141(3.3V) J2.147(3.3V) J2.153(3.3V) J2.159(3.3V) J18.4 R198.2 R209.2 R338.1 U4.A5(VCC) U4.B5(VCC) U4.C5(VCC) U4.D1(AVCC) U4.D2(AVCC) U4.E7(VCC) U4.E8(VCC) U4.G1(VCC) U6.4(VCC) U23.C4(VCCIO2) U23.C8(VCCIO2) U23.E3(VCCIO1) U23.G9(VCCIO2) U23.J4(VCCIO1) U23.J8(VCCIO1) U31.14(VCCO) U34.1(VCCI) U49.9(VCCIO1) U49.31(VCCIO1) U49.45(VCCIO1) U51.4(VCC) ; also on sheet 8 14 16 23 24 25 26 27 28
5.0V: J10.3 J10.10 R172.2 R173.2 R234.2 R235.2 U12.7(VCC) U38.7(VCC) ; also on sheet 23 26 27 29
12V: C129.1 C131.1 J1.46(12V) J1.52(12V) J1.58(12V) J1.64(12V) J1.70(12V) J1.76(12V) J1.82(12V) J1.88(12V) J1.94(12V) J1.100(12V) J1.106(12V) J1.112(12V) J1.118(12V) J1.124(12V) J1.130(12V) J1.136(12V) J1.142(12V) J1.148(12V) J1.154(12V) J2.46(12V) J2.52(12V) J2.58(12V) J2.64(12V) J2.70(12V) J2.76(12V) J2.82(12V) J2.88(12V) J2.94(12V) J2.100(12V) J2.106(12V) J2.112(12V) J2.118(12V) J2.124(12V) J2.130(12V) J2.136(12V) J2.142(12V) J2.148(12V) J2.154(12V) ; also on sheet 23 24 25 26 27 28 29
GND: C13.2 C35.2 C36.2 C37.2 C38.2 C44.2 C45.2 C47.2 C50.2 C53.2 C58.2 C59.2 C60.2 C61.2 C67.2 C79.2 C80.2 C84.2 C86.2 C96.2 C104.2 C105.2 C121.2 C122.2 C128.2 C129.2 C130.2 C131.2 C132.2 C133.2 C149.2 C150.2 C156.2 C157.2 C158.2 C173.2 C174.2 C185.2 C205.2 C206.2 C210.2 C211.1 C262.1 C263.1 C294.1 C318.1 C345.2 C421.2 C422.2 C433.2 C434.2 C439.2 C440.2 C461.2 C480.2 J1.161(GND_1_1) J1.162(GND_1_2) J1.163(GND_1_3) J1.164(GND_1_4) J1.165(GND_2_1) J1.166(GND_2_2) J1.167(GND_2_3) J1.168(GND_2_4) J1.169(GND_3_1) J1.170(GND_3_2) J1.171(GND_3_3) J1.172(GND_3_4) J2.161(GND_1_1) J2.162(GND_1_2) J2.163(GND_1_3) J2.164(GND_1_4) J2.165(GND_2_1) J2.166(GND_2_2) J2.167(GND_2_3) J2.168(GND_2_4) J2.169(GND_3_1) J2.170(GND_3_2) J2.171(GND_3_3) J2.172(GND_3_4) J5.5(SHIELD) J9.10(GND) J9.11(GND_TAB) J9.12(GND_TAB) J10.2 J10.9 J18.2 J18.10 R18.1 R35.2 R44.1 R49.1 R176.1 R202.2 R304.1 R333.1 S1.1 S2.1 S3.1 S4.1 S5.1 S6.1 S7.1 SW1.1(A1) SW1.2(A2) SW1.3(A3) SW1.4(A4) SW1.5(A5) SW1.6(A6) SW1.7(A7) SW1.8(A8) SW4.5(B4) SW4.6(B3) SW4.7(B2) SW4.8(B1) U4.A4(GND) U4.B4(GND) U4.C4(GND) U4.D7(GND) U4.D8(GND) U4.F1(AGND) U4.F2(AGND) U4.H1(GND) U4.H2(RESERVED) U5.3(GND) U6.1(GND) U11.7(TX_ER) U11.17(TXD4) U11.18(TXD5) U11.19(TXD6) U11.20(TXD7) U11.27(COMA) U11.53(VSSC) U11.61(CONFIG3) U11.64(CONFIG1) U11.65(CONFIG0) U11.97(VSS) U12.2(GND) U23.C5(GNDINT) U23.D5(GNDIO) U23.D7(GNDIO) U23.E4(GNDIO) U23.E8(GNDINT) U23.G4(GNDINT) U23.G8(GNDIO) U23.H5(GNDIO) U23.H7(GNDIO) U23.J5(GNDINT) U31.6(A4) U31.7(GND) U31.8(~{OE}) U31.9(Y4) U31.15(GND_EPAD) U34.6(A4) U34.7(GND) U34.8(~{OE}) U34.9(Y4) U34.15(GND_EPAD) U38.2(GND) U49.10(GNDIO) U49.11(GNDINT) U49.32(GNDIO) U49.37(GNDINT) U49.46(GNDIO) U49.60(GNDIO) U49.65(GNDINT) U49.79(GNDIO) U49.90(GNDINT) U49.93(GNDIO) U51.1(GND) X1.2(GND) Y1.2 Y1.4 ; also on sheet 3 4 6 7 8 9 10 11 12 13 14 15 16 22 23 24 25 26 27 28 29 30
GND_EARTH: C13.1 J5.6(SHIELD2) J5.7(SHIELD3) R18.2
VBUS_5V: J5.1(VBUS) R177.1
24M_XTALIN: C150.1 U4.C1(XTALIN) Y1.1
24M_XTALOUT: C149.1 U4.C2(XTALOUT) Y1.3
ASSP_CLK: U31.2(A0) ; also on sheet 4
ASSP_CPLD_MAX_TCK: R334.2 U23.K1(TCK)
ASSP_CPLD_MAX_TDI: R329.2 U23.J2(TDI)
ASSP_CPLD_MAX_TDO: R336.2 U23.K2(TDO)
ASSP_CPLD_MAX_TMS: R321.2 U23.J1(TMS)
ASSP_CPLD_MRn: U51.3(~{MR}) ; also on sheet 15
ASSP_CPLD_RESETn: R304.2 U23.K8(IOB1/DEV_CLRn) U51.2(~{RESET})
ASSP_DATAOUT: U34.12(Y1) ; also on sheet 4
ASSP_MODE: R356.1 SW4.4(A4) ; also on sheet 15
ASSP_RANDOM_IN: U31.4(A2) ; also on sheet 4
ASSP_RUN_IN: U31.5(A3) ; also on sheet 4
ASSP_SHIFT_EN: U34.13(Y0) ; also on sheet 4
ASSP_SYS_RESET: U31.3(A1) ; also on sheet 4
ASSP_TEST1: U34.11(Y2) ; also on sheet 4
ASSP_TEST2: U34.10(Y3) ; also on sheet 4
C_JTAG_TCK: R75.2 U49.36(IOB1_24)
C_JTAG_TDI: R82.2 U49.50(IOB1_32)
C_JTAG_TDO: R85.2 U49.48(IOB1_30)
C_JTAG_TMS: R81.2 U49.49(IOB1_31)
C_USB_MAX_TCK: R62.1 R335.2 U49.24(TCK)
C_USB_MAX_TDI: R60.1 R328.2 U49.23(TDI)
C_USB_MAX_TDO: R63.1 R337.2 U49.25(TDO)
C_USB_MAX_TMS: R61.1 R322.2 U49.22(TMS)
CLK_ENABLE: R346.1 SW4.2(A2) ; also on sheet 15
CLK_SEL: R341.1 SW4.1(A1) ; also on sheet 8 15
CPU_RESETn: R128.1 S4.2 ; also on sheet 10 15
DISP_I2C_SCL: U12.5(VL_IO1) ; also on sheet 4
DISP_I2C_SDA: U12.4(VL_IO2) ; also on sheet 4
DISP_SPISS: U38.5(VL_IO1) ; also on sheet 4
ENET_DVDD: C36.1 C38.1 C47.1 C59.1 C60.1 U11.1(DVDD) U11.6(DVDD) U11.10(DVDD) U11.15(DVDD) U11.57(DVDD) U11.62(DVDD) U11.67(DVDD) U11.71(DVDD) U11.85(DVDD) ; also on sheet 27
ENET_GTX_CLK: U11.8(GTX_CLK) ; also on sheet 4
ENET_INTn: R39.1 U11.23(INT_N) ; also on sheet 4
ENET_LED_DUPLEX: U11.60(CONFIG4) U11.70(LED_DUPLEX)
ENET_LED_LINK10: R208.1 U11.76(LED_LINK10)
ENET_LED_LINK100: R207.1 U11.74(LED_LINK100)
ENET_LED_LINK1000: R206.1 U11.73(LED_LINK1000)
ENET_LED_RX: R211.1 U11.58(CONFIG6) U11.69(LED_RX)
ENET_LED_TX: R212.1 U11.68(LED_TX)
ENET_MDC: R40.1 U11.25(MDC) ; also on sheet 4
ENET_MDIO: R38.1 U11.24(MDIO) ; also on sheet 4
ENET_RESETn: R43.1 U11.28(RESET_N) ; also on sheet 4
ENET_RSET: R44.2 U11.30(RSET)
ENET_RX_CLK: U11.2(RXCLK) ; also on sheet 4
ENET_RX_D0: U11.95(RXD0) ; also on sheet 4
ENET_RX_D1: U11.92(RXD1) ; also on sheet 4
ENET_RX_D2: U11.93(RXD2) ; also on sheet 4
ENET_RX_D3: U11.91(RXD3) ; also on sheet 4
ENET_RX_DV: U11.94(RX_DV) ; also on sheet 4
ENET_TX_D0: U11.11(TXD0) ; also on sheet 4
ENET_TX_D1: U11.12(TXD1) ; also on sheet 4
ENET_TX_D2: U11.14(TXD2) ; also on sheet 4
ENET_TX_D3: U11.16(TXD3) ; also on sheet 4
ENET_TX_EN: U11.9(TX_EN) ; also on sheet 4
ENET_XTAL_25MHZ: U11.55(XTAL1) X1.3(OUT)
EXTRA_SIG0: U49.7(IOB1) ; also on sheet 15
EXTRA_SIG1: U49.72(IOB2_15) ; also on sheet 15
EXTRA_SIG2: U49.98(IOB2_35) ; also on sheet 15
FACTORY_REQUEST: R80.2 U49.56(IOB2_5) ; also on sheet 15
FACTORY_STATUS: U49.68(IOB2_11) ; also on sheet 15
FACTORY_USER: R347.1 SW4.3(A3) ; also on sheet 15
FX2_D_N: J5.2(D-) U4.E1(DMINUS) U5.2(D-)
FX2_D_P: J5.3(D+) U4.E2(DPLUS) U5.1(D+)
FX2_FLAGA: U4.H7(CTL0) U49.51(IOB1_4)
FX2_FLAGB: U4.G7(CTL1) U49.17(IOB1_11)
FX2_FLAGC: U4.H8(CTL2) U49.3(IOB1_2)
FX2_PA1: U4.G6(PA1) U49.19(IOB1_13)
FX2_PA2: U4.F8(PA2) U49.2(IOB1_1)
FX2_PA3: U4.F7(PA3) U49.5(IOB1)
FX2_PA4: U4.F6(PA4) U49.6(IOB1)
FX2_PA5: U4.C8(PA5) U49.47(IOB1_29)
FX2_PA6: U4.C7(PA6) U49.15(IOB1_9)
FX2_PA7: U4.C6(PA7) U49.4(IOB1_3)
FX2_PB0: U4.H3(PB0) U49.18(IOB1_12)
FX2_PB1: U4.F4(PB1) U49.28(IOB1_18)
FX2_PB2: U4.H4(PB2) U49.16(IOB1_10)
FX2_PB3: U4.G4(PB3) U49.29(IOB1_19)
FX2_PB4: U4.H5(PB4) U49.8(IOB1)
FX2_PB5: U4.G5(PB5) U49.20(IOB1_14)
FX2_PB6: U4.F5(PB6) U49.27(IOB1_17)
FX2_PB7: U4.H6(PB7) U49.14(IOB1/GCLK1)
FX2_PD0: R62.2 U4.A8(PD0)
FX2_PD1: R61.2 U4.A7(PD1)
FX2_PD2: R60.2 U4.B6(PD2)
FX2_PD3: R63.2 U4.A6(PD3)
FX2_PD4: U4.B3(PD4) U49.34(IOB1_22)
FX2_PD5: U4.A3(PD5) U49.42(IOB1_28)
FX2_PD6: U4.C3(PD6) U49.33(IOB1_21)
FX2_PD7: U4.A2(PD7) U49.41(IOB1_27)
FX2_RESETn: R202.1 U4.B8(~{RESET}) U6.2(~{RESET}) U49.44(IOB1/DEV_CLRn)
FX2_SCL: R198.1 U4.F3(SCL) U49.30(IOB1_20)
FX2_SDA: R209.1 R210.1 U4.G3(SDA)
FX2_SLRDn: U4.A1(RDY0) U49.40(IOB1_26)
FX2_SLWRn: U4.B1(RDY1) U49.35(IOB1_23)
FX2_WAKEUP: C157.1 R176.2 R177.2 U4.B7(WAKEUP)
HSMA_CLK_IN0: J1.40 ; also on sheet 6
HSMA_CLK_IN_N1: J1.98 ; also on sheet 9
HSMA_CLK_IN_N2: J1.158 ; also on sheet 9
HSMA_CLK_IN_P1: J1.96 ; also on sheet 9
HSMA_CLK_IN_P2: J1.156 ; also on sheet 9
HSMA_CLK_OUT0: J1.39 ; also on sheet 6
HSMA_CLK_OUT_N1: J1.97 ; also on sheet 6
HSMA_CLK_OUT_N2: J1.157 ; also on sheet 9
HSMA_CLK_OUT_P1: J1.95 ; also on sheet 6
HSMA_CLK_OUT_P2: J1.155 ; also on sheet 9
HSMA_D0: J1.41 ; also on sheet 6
HSMA_D1: J1.42 ; also on sheet 6
HSMA_D2: J1.43 ; also on sheet 6
HSMA_D3: J1.44 ; also on sheet 6
HSMA_JTAG_TDO: J1.37 ; also on sheet 11
HSMA_JTAG_TMS: J1.36 ; also on sheet 11
HSMA_PRSNTn: J1.160(PSNTn) R112.1 ; also on sheet 6 15
HSMA_RX_CN0: J1.32 R141.2
HSMA_RX_CN1: J1.28 R161.2
HSMA_RX_CN2: J1.24 R168.2
HSMA_RX_CN3: J1.20 R170.2
HSMA_RX_CP0: J1.30 R142.2
HSMA_RX_CP1: J1.26 R162.2
HSMA_RX_CP2: J1.22 R169.2
HSMA_RX_CP3: J1.18 R171.2
HSMA_RX_D_N0: J1.50 ; also on sheet 6
HSMA_RX_D_N1: J1.56 ; also on sheet 6
HSMA_RX_D_N2: J1.62 ; also on sheet 6
HSMA_RX_D_N3: J1.68 ; also on sheet 6
HSMA_RX_D_N4: J1.74 ; also on sheet 6
HSMA_RX_D_N5: J1.80 ; also on sheet 6
HSMA_RX_D_N6: J1.86 ; also on sheet 6
HSMA_RX_D_N7: J1.92 ; also on sheet 6
HSMA_RX_D_N8: J1.104 ; also on sheet 6
HSMA_RX_D_N9: J1.110 ; also on sheet 6
HSMA_RX_D_N10: J1.116 ; also on sheet 6
HSMA_RX_D_N11: J1.122 ; also on sheet 6
HSMA_RX_D_N12: J1.128 ; also on sheet 6
HSMA_RX_D_N13: J1.134 ; also on sheet 6
HSMA_RX_D_N14: J1.140 ; also on sheet 6
HSMA_RX_D_N15: J1.146 ; also on sheet 6
HSMA_RX_D_N16: J1.152 ; also on sheet 6
HSMA_RX_D_P0: J1.48 ; also on sheet 6
HSMA_RX_D_P1: J1.54 ; also on sheet 6
HSMA_RX_D_P2: J1.60 ; also on sheet 6
HSMA_RX_D_P3: J1.66 ; also on sheet 6
HSMA_RX_D_P4: J1.72 ; also on sheet 6
HSMA_RX_D_P5: J1.78 ; also on sheet 6
HSMA_RX_D_P6: J1.84 ; also on sheet 6
HSMA_RX_D_P7: J1.90 ; also on sheet 6
HSMA_RX_D_P8: J1.102 ; also on sheet 6
HSMA_RX_D_P9: J1.108 ; also on sheet 6
HSMA_RX_D_P10: J1.114 ; also on sheet 6
HSMA_RX_D_P11: J1.120 ; also on sheet 6
HSMA_RX_D_P12: J1.126 ; also on sheet 6
HSMA_RX_D_P13: J1.132 ; also on sheet 6
HSMA_RX_D_P14: J1.138 ; also on sheet 6
HSMA_RX_D_P15: J1.144 ; also on sheet 6
HSMA_RX_D_P16: J1.150 ; also on sheet 6
HSMA_RX_LED: D19.2(CATHODE) ; also on sheet 6
HSMA_RX_N0: R141.1 ; also on sheet 7
HSMA_RX_N1: R161.1 ; also on sheet 7
HSMA_RX_N2: R168.1 ; also on sheet 7
HSMA_RX_N3: R170.1 ; also on sheet 7
HSMA_RX_P0: R142.1 ; also on sheet 7
HSMA_RX_P1: R162.1 ; also on sheet 7
HSMA_RX_P2: R169.1 ; also on sheet 7
HSMA_RX_P3: R171.1 ; also on sheet 7
HSMA_SCL: J1.34 ; also on sheet 6
HSMA_SDA: J1.33 ; also on sheet 6
HSMA_TX_D_N0: J1.49 ; also on sheet 6
HSMA_TX_D_N1: J1.55 ; also on sheet 6
HSMA_TX_D_N2: J1.61 ; also on sheet 6
HSMA_TX_D_N3: J1.67 ; also on sheet 6
HSMA_TX_D_N4: J1.73 ; also on sheet 6
HSMA_TX_D_N5: J1.79 ; also on sheet 6
HSMA_TX_D_N6: J1.85 ; also on sheet 6
HSMA_TX_D_N7: J1.91 ; also on sheet 6
HSMA_TX_D_N8: J1.103 ; also on sheet 6
HSMA_TX_D_N9: J1.109 ; also on sheet 6
HSMA_TX_D_N10: J1.115 ; also on sheet 6
HSMA_TX_D_N11: J1.121 ; also on sheet 6
HSMA_TX_D_N12: J1.127 ; also on sheet 6
HSMA_TX_D_N13: J1.133 ; also on sheet 6
HSMA_TX_D_N14: J1.139 ; also on sheet 6
HSMA_TX_D_N15: J1.145 ; also on sheet 6
HSMA_TX_D_N16: J1.151 ; also on sheet 6
HSMA_TX_D_P0: J1.47 ; also on sheet 6
HSMA_TX_D_P1: J1.53 ; also on sheet 6
HSMA_TX_D_P2: J1.59 ; also on sheet 6
HSMA_TX_D_P3: J1.65 ; also on sheet 6
HSMA_TX_D_P4: J1.71 ; also on sheet 6
HSMA_TX_D_P5: J1.77 ; also on sheet 6
HSMA_TX_D_P6: J1.83 ; also on sheet 6
HSMA_TX_D_P7: J1.89 ; also on sheet 6
HSMA_TX_D_P8: J1.101 ; also on sheet 6
HSMA_TX_D_P9: J1.107 ; also on sheet 6
HSMA_TX_D_P10: J1.113 ; also on sheet 6
HSMA_TX_D_P11: J1.119 ; also on sheet 6
HSMA_TX_D_P12: J1.125 ; also on sheet 6
HSMA_TX_D_P13: J1.131 ; also on sheet 6
HSMA_TX_D_P14: J1.137 ; also on sheet 6
HSMA_TX_D_P15: J1.143 ; also on sheet 6
HSMA_TX_D_P16: J1.149 ; also on sheet 6
HSMA_TX_LED: D20.2(CATHODE) ; also on sheet 6
HSMA_TX_N0: J1.31 ; also on sheet 7
HSMA_TX_N1: J1.27 ; also on sheet 7
HSMA_TX_N2: J1.23 ; also on sheet 7
HSMA_TX_N3: J1.19 ; also on sheet 7
HSMA_TX_P0: J1.29 ; also on sheet 7
HSMA_TX_P1: J1.25 ; also on sheet 7
HSMA_TX_P2: J1.21 ; also on sheet 7
HSMA_TX_P3: J1.17 ; also on sheet 7
HSMB_A0: J2.50 ; also on sheet 6
HSMB_A1: J2.54 ; also on sheet 6
HSMB_A2: J2.56 ; also on sheet 6
HSMB_A3: J2.60 ; also on sheet 6
HSMB_A4: J2.62 ; also on sheet 6
HSMB_A5: J2.74 ; also on sheet 6
HSMB_A6: J2.78 ; also on sheet 6
HSMB_A7: J2.80 ; also on sheet 6
HSMB_A8: J2.84 ; also on sheet 6
HSMB_A9: J2.86 ; also on sheet 6
HSMB_A10: J2.104 ; also on sheet 6
HSMB_A11: J2.108 ; also on sheet 6
HSMB_A12: J2.110 ; also on sheet 6
HSMB_A13: J2.114 ; also on sheet 6
HSMB_A14: J2.116 ; also on sheet 6
HSMB_A15: J2.128 ; also on sheet 6
HSMB_ADDR_CMD0: J2.43 ; also on sheet 6
HSMB_BA0: J2.132 ; also on sheet 6
HSMB_BA1: J2.134 ; also on sheet 6
HSMB_BA2: J2.138 ; also on sheet 6
HSMB_BA3: J2.140 ; also on sheet 6
HSMB_C_N: J2.151 ; also on sheet 6
HSMB_C_P: J2.149 ; also on sheet 6
HSMB_CASn: J2.44 ; also on sheet 6
HSMB_CKE: J2.150 ; also on sheet 6
HSMB_CLK_IN0: J2.40 ; also on sheet 6
HSMB_CLK_IN_N1: J2.98 ; also on sheet 6
HSMB_CLK_IN_N2: J2.158 ; also on sheet 9
HSMB_CLK_IN_P1: J2.96 ; also on sheet 6
HSMB_CLK_IN_P2: J2.156 ; also on sheet 9
HSMB_CLK_OUT0: J2.39 ; also on sheet 6
HSMB_CLK_OUT_N1: J2.97 ; also on sheet 6
HSMB_CLK_OUT_N2: J2.157 ; also on sheet 6
HSMB_CLK_OUT_P1: J2.95 ; also on sheet 6
HSMB_CLK_OUT_P2: J2.155 ; also on sheet 6
HSMB_CSn: J2.152 ; also on sheet 6
HSMB_DM0: J2.48 ; also on sheet 6
HSMB_DM1: J2.72 ; also on sheet 6
HSMB_DM2: J2.102 ; also on sheet 6
HSMB_DM3: J2.126 ; also on sheet 6
HSMB_DQ0: J2.47 ; also on sheet 6
HSMB_DQ1: J2.49 ; also on sheet 6
HSMB_DQ2: J2.53 ; also on sheet 6
HSMB_DQ3: J2.55 ; also on sheet 6
HSMB_DQ4: J2.59 ; also on sheet 6
HSMB_DQ5: J2.61 ; also on sheet 6
HSMB_DQ6: J2.65 ; also on sheet 6
HSMB_DQ7: J2.67 ; also on sheet 6
HSMB_DQ8: J2.71 ; also on sheet 6
HSMB_DQ9: J2.73 ; also on sheet 6
HSMB_DQ10: J2.77 ; also on sheet 6
HSMB_DQ11: J2.79 ; also on sheet 6
HSMB_DQ12: J2.83 ; also on sheet 6
HSMB_DQ13: J2.85 ; also on sheet 6
HSMB_DQ14: J2.89 ; also on sheet 6
HSMB_DQ15: J2.91 ; also on sheet 6
HSMB_DQ16: J2.101 ; also on sheet 6
HSMB_DQ17: J2.103 ; also on sheet 6
HSMB_DQ18: J2.107 ; also on sheet 6
HSMB_DQ19: J2.109 ; also on sheet 6
HSMB_DQ20: J2.113 ; also on sheet 6
HSMB_DQ21: J2.115 ; also on sheet 6
HSMB_DQ22: J2.119 ; also on sheet 6
HSMB_DQ23: J2.121 ; also on sheet 6
HSMB_DQ24: J2.125 ; also on sheet 6
HSMB_DQ25: J2.127 ; also on sheet 6
HSMB_DQ26: J2.131 ; also on sheet 6
HSMB_DQ27: J2.133 ; also on sheet 6
HSMB_DQ28: J2.137 ; also on sheet 6
HSMB_DQ29: J2.139 ; also on sheet 6
HSMB_DQ30: J2.143 ; also on sheet 6
HSMB_DQ31: J2.145 ; also on sheet 6
HSMB_DQS_N0: J2.68 ; also on sheet 6
HSMB_DQS_N1: J2.92 ; also on sheet 6
HSMB_DQS_N2: J2.122 ; also on sheet 6
HSMB_DQS_N3: J2.146 ; also on sheet 6
HSMB_DQS_P0: J2.66 ; also on sheet 6
HSMB_DQS_P1: J2.90 ; also on sheet 6
HSMB_DQS_P2: J2.120 ; also on sheet 6
HSMB_DQS_P3: J2.144 ; also on sheet 6
HSMB_JTAG_TDI: J2.38 ; also on sheet 11
HSMB_JTAG_TDO: J2.37 ; also on sheet 11
HSMB_JTAG_TMS: J2.36 ; also on sheet 11
HSMB_PRSNTn: J2.160(PSNTn) R108.1 ; also on sheet 6 15
HSMB_RASn: J2.42 ; also on sheet 6
HSMB_RX_CN0: J2.32 R110.2
HSMB_RX_CN1: J2.28 R116.2
HSMB_RX_CN2: J2.24 R125.2
HSMB_RX_CN3: J2.20 R167.2
HSMB_RX_CP0: J2.30 R115.2
HSMB_RX_CP1: J2.26 R124.2
HSMB_RX_CP2: J2.22 R149.2
HSMB_RX_CP3: J2.18 R150.2
HSMB_RX_LED: D3.2(CATHODE) ; also on sheet 6
HSMB_RX_N0: R110.1 ; also on sheet 7
HSMB_RX_N1: R116.1 ; also on sheet 7
HSMB_RX_N2: R125.1 ; also on sheet 7
HSMB_RX_N3: R167.1 ; also on sheet 7
HSMB_RX_P0: R115.1 ; also on sheet 7
HSMB_RX_P1: R124.1 ; also on sheet 7
HSMB_RX_P2: R149.1 ; also on sheet 7
HSMB_RX_P3: R150.1 ; also on sheet 7
HSMB_SCL: J2.34 ; also on sheet 6
HSMB_SDA: J2.33 ; also on sheet 6
HSMB_TX_LED: D4.2(CATHODE) ; also on sheet 6
HSMB_TX_N0: J2.31 ; also on sheet 7
HSMB_TX_N1: J2.27 ; also on sheet 7
HSMB_TX_N2: J2.23 ; also on sheet 7
HSMB_TX_N3: J2.19 ; also on sheet 7
HSMB_TX_P0: J2.29 ; also on sheet 7
HSMB_TX_P1: J2.25 ; also on sheet 7
HSMB_TX_P2: J2.21 ; also on sheet 7
HSMB_TX_P3: J2.17 ; also on sheet 7
HSMB_WEn: J2.41 ; also on sheet 6
I2C_SCL_DISP: J10.7 R234.1 U12.8(VCCIO1)
I2C_SDA_DISP: J10.8 R235.1 U12.1(VCCIO2)
JTAG_BLASTER_TDI: R82.1 R302.2 ; also on sheet 11 15
JTAG_BLASTER_TDO: R85.1 ; also on sheet 10 11
JTAG_FPGA_TDO: J1.38 ; also on sheet 10 11
JTAG_RX: D27.2(CATHODE) U49.55(IOB2_4)
JTAG_TCK: J1.35 J2.35 R75.1 R109.1 R111.1 ; also on sheet 10 11 15
JTAG_TMS: R81.1 ; also on sheet 10 11 15
JTAG_TX: D28.2(CATHODE) U49.52(IOB2_1)
M570_CLOCK: U49.64(IOB2/GCLK3) ; also on sheet 15
M570_PCIE_JTAG_EN: U49.70(IOB2_13) ; also on sheet 15
MAX_CONF_DONE: D7.2(CATHODE) ; also on sheet 15
MAX_ERROR: D5.2(CATHODE) ; also on sheet 15
MAX_LOAD: D6.2(CATHODE) ; also on sheet 15
MAX_RESETn: R350.1 S7.2 ; also on sheet 15
MAX_SDA: R210.2 U49.43(IOB1/DEV_OE)
MDI_N0: J9.2(TD0_N) R230.2 U11.31(MDI0_N)
MDI_N1: J9.6(TD1_N) R240.2 U11.34(MDI1_N)
MDI_N2: J9.5(TD2_N) R239.2 U11.41(MDI2_N)
MDI_N3: J9.8(TD3_N) R247.2 U11.43(MDI3_N)
MDI_P0: J9.1(TD0_P) R229.2 U11.29(MDI0_P)
MDI_P1: J9.3(TD1_P) R231.2 U11.33(MDI1_P)
MDI_P2: J9.4(TD2_P) R238.2 U11.39(MDI2_P)
MDI_P3: J9.7(TD3_P) R246.2 U11.42(MDI3_P)
PCIE_LED_X1: D35.2(CATHODE) D44.2(CATHODE) ; also on sheet 4
PCIE_LED_X4: D34.2(CATHODE) D45.2(CATHODE) ; also on sheet 4
PGM_CONFIG: R127.1 S5.2 ; also on sheet 15
PGM_LED0: D14.2(CATHODE) ; also on sheet 15
PGM_LED1: D13.2(CATHODE) ; also on sheet 15
PGM_LED2: D12.2(CATHODE) ; also on sheet 15
PGM_SEL: R126.1 S6.2 ; also on sheet 15
RES_CONF_DONE1n: D7.1(ANODE) R146.1
RES_MAX_ERROR1: D5.1(ANODE) R148.1
RES_MAX_LOAD1: D6.1(ANODE) R147.1
RESn_HSMA_RX_LED: D19.1(ANODE) R152.1
RESn_HSMA_TX_LED: D20.1(ANODE) R151.1
RESn_HSMB_RX_LED: D3.1(ANODE) R114.1
RESn_HSMB_TX_LED: D4.1(ANODE) R113.1
RESn_JTAG_RX: D27.1(ANODE) R262.1
RESn_JTAG_TX: D28.1(ANODE) R261.1
RESn_LED0: D18.1(ANODE) R153.1
RESn_LED1: D17.1(ANODE) R154.1
RESn_LED2: D16.1(ANODE) R155.1
RESn_LED3: D15.1(ANODE) R156.1
RESn_LED4: D11.1(ANODE) R129.1
RESn_LED5: D10.1(ANODE) R130.1
RESn_LED6: D9.1(ANODE) R131.1
RESn_LED7: D8.1(ANODE) R132.1
RESn_PGM1_LED0: D14.1(ANODE) R163.1
RESn_PGM1_LED1: D13.1(ANODE) R164.1
RESn_PGM1_LED2: D12.1(ANODE) R165.1
RESn_SC_RX: D29.1(ANODE) R260.1
RESn_SC_TX: D30.1(ANODE) R259.1
SC_CLK: U23.E1(IOB1/GCLK1) U31.13(Y0)
SC_DATAIN: U23.C11(IOB2_23) U31.11(Y2)
SC_DATAOUT: U23.C1(IOB1_2) U34.3(A1)
SC_RX: D29.2(CATHODE) U49.53(IOB2_2)
SC_SHIFT_EN: U23.J11(IOB2_37) U34.2(A0)
SC_SYS_RESET: U23.G11(IOB2/GCLK3) U31.12(Y1)
SC_TEST1: U23.A1(IOB2_1) U34.4(A2)
SC_TEST2: U23.H11(IOB2_34) U34.5(A3)
SC_TX: D30.2(CATHODE) U49.54(IOB2_3)
SC_V_IN: U23.E11(IOB2_29) U31.10(Y3)
SPI_SS_DISP: J10.5 R173.1 U38.8(VCCIO1)
SW_USB_MAX_TCK: J18.1 R333.2 R334.1 R335.1
SW_USB_MAX_TDI: J18.9 R328.1 R329.1
SW_USB_MAX_TDO: J18.3 R336.1 R337.1
SW_USB_MAX_TMS: J18.5 R321.1 R322.1 R338.2
USB_ADDR0: U49.85(IOB2_26) ; also on sheet 4
USB_ADDR1: U49.86(IOB2_27) ; also on sheet 4
USB_CFG0: U49.97(IOB2_34) ; also on sheet 15
USB_CFG1: U49.99(IOB2_36) ; also on sheet 15
USB_CFG2: U49.100(IOB2_37) ; also on sheet 15
USB_CFG3: U49.69(IOB2_12) ; also on sheet 15
USB_CFG4: U49.71(IOB2_14) ; also on sheet 15
USB_CFG5: U49.57(IOB2_6) ; also on sheet 15
USB_CFG6: U49.73(IOB2_16) ; also on sheet 15
USB_CFG7: U49.62(IOB2/GCLK2) ; also on sheet 15
USB_CFG8: U49.84(IOB2_25) ; also on sheet 15
USB_CFG9: U49.1(IOB2_38) ; also on sheet 15
USB_CFG10: U49.96(IOB2_33) ; also on sheet 15
USB_CFG11: U49.92(IOB2_31) ; also on sheet 15
USB_CLK: U4.G2(IFCLK) U49.12(IOB1/GCLK0) ; also on sheet 9 15
USB_DATA0: U49.74(IOB2_17) ; also on sheet 4
USB_DATA1: U49.75(IOB2_18) ; also on sheet 4
USB_DATA2: U49.76(IOB2_19) ; also on sheet 4
USB_DATA3: U49.77(IOB2_20) ; also on sheet 4
USB_DATA4: U49.78(IOB2_21) ; also on sheet 4
USB_DATA5: U49.81(IOB2_22) ; also on sheet 4
USB_DATA6: U49.82(IOB2_23) ; also on sheet 4
USB_DATA7: U49.83(IOB2_24) ; also on sheet 4
USB_DISABLEn: U49.21(IOB1_15) ; also on sheet 11
USB_EMPTY: R76.2 U49.89(IOB2_29) ; also on sheet 4
USB_FULL: R77.2 U49.87(IOB2_28) ; also on sheet 4
USB_OEn: U49.61(IOB2_8) ; also on sheet 4
USB_RDn: U49.66(IOB2_9) ; also on sheet 9
USB_RESETn: U49.58(IOB2_7) ; also on sheet 9
USB_SCL: R74.2 U49.91(IOB2_30) ; also on sheet 4
USB_SDA: R68.2 U49.95(IOB2_32) ; also on sheet 4
USB_WRn: U49.67(IOB2_10) ; also on sheet 4
USER_DIPSW0: R140.1 SW1.16(B1) ; also on sheet 6
USER_DIPSW1: R139.1 SW1.15(B2) ; also on sheet 6
USER_DIPSW2: R138.1 SW1.14(B3) ; also on sheet 6
USER_DIPSW3: R137.1 SW1.13(B4) ; also on sheet 6
USER_DIPSW4: R136.1 SW1.12(B5) ; also on sheet 6
USER_DIPSW5: R135.1 SW1.11(B6) ; also on sheet 6
USER_DIPSW6: R134.1 SW1.10(B7) ; also on sheet 6
USER_DIPSW7: R133.1 SW1.9(B8) ; also on sheet 6
USER_LED0: D18.2(CATHODE) ; also on sheet 4
USER_LED1: D17.2(CATHODE) ; also on sheet 4
USER_LED2: D16.2(CATHODE) ; also on sheet 4
USER_LED3: D15.2(CATHODE) ; also on sheet 4
USER_LED4: D11.2(CATHODE) ; also on sheet 4
USER_LED5: D10.2(CATHODE) ; also on sheet 4
USER_LED6: D9.2(CATHODE) ; also on sheet 4
USER_LED7: D8.2(CATHODE) ; also on sheet 4
USER_PB0: R143.1 S3.2 ; also on sheet 4
USER_PB1: R144.1 S2.2 ; also on sheet 4
USER_PB2: R145.1 S1.2 ; also on sheet 4
N47341691: D22.2(CATHODE) R212.2
N47341693: D25.2(CATHODE) R207.2
N47341697: D23.2(CATHODE) R211.2
N47341701: D26.2(CATHODE) R206.2
N47342317: C318.2 R246.1 R247.1
N47342360: C263.2 R231.1 R240.1
N47342381: C262.2 R229.1 R230.1
N47342387: C294.2 R238.1 R239.1
N47342610: R49.2 U11.47(TRST_N)
N48585293: D34.1(ANODE) R358.1
N48585297: D35.1(ANODE) R357.1
N53011114: D1.2(CATHODE) R112.2
N58890372: R52.1 X1.1(EN)
N120137011: J5.4(GND) R35.1
N121402807: D24.2(CATHODE) R208.2
N126461283: D2.2(CATHODE) R108.2
N127173874: R241.1 U12.3(VL) U12.6(\\~{TRI_STAT}E)
N127609781: D45.1(ANODE) R104.1
N127610138: D44.1(ANODE) R105.1
N128414621: C132.1 R111.2
N128415220: C133.1 R109.2
N128431452: R172.1 U38.1(VCCIO2)
N128431480: R179.1 U38.3(VL) U38.6(\\~{TRI_STAT}E)

Not connected (* = marked no-connect by the designer): J1 1* 2* 3* 4* 5* 6* 7* 8* 9* 10* 11* 12* 13* 14* 15* 16*; J2 1* 2* 3* 4* 5* 6* 7* 8* 9* 10* 11* 12* 13* 14* 15* 16*; J10 1* 4* 6*; J18 6* 7* 8*; U4 B2(CLKOUT)* G8(PA0)*; U6 3(~{MR})*; U11 3(RX_ER)* 4(TX_CLK)* 13(NC1)* 22(125CLK)* 37(HSDAC_P) 38(HSDAC_N) 44(TDI)* 46(TMS)* 49(TCK)* 50(TDO)* 51(NC2)* 54(XTAL2)* 56(SEL_FREQ)* 75(S_OUT_N)* 77(S_OUT_P)* 79(S_CLK_P)* 80(S_CLK_N)* 81(S_IN_N)* 82(S_IN_P)* 83(COL)* 84(CRS)* 86(RXD7)* 87(RXD6)* 89(RXD5)* 90(RXD4)*; U23 A2(IOB2_4) A3(IOB2_5) A4(IOB2_6) A5(IOB2_7) A6(IOB2_8) A7(IOB2_9) A8(IOB2_10) A9(IOB2_11) A10(IOB2_2) A11(IOB2_3) B1(IOB1_1)* B2(IOB2_14) B3(IOB2_15) B4(IOB2_16) B5(IOB2_17) B6(IOB2_18) B7(IOB2_19) B8(IOB2_20) B9(IOB2_21) B10(IOB2_12) B11(IOB2_13) C2(IOB1_3)* C6(IOB2_24) C10(IOB2_22) D1(IOB1_4)* D2(IOB1_5)* D3(IOB1_6)* D9(IOB2_27) D10(IOB2_25) D11(IOB2_26) E2(IOB1_7)* E10(IOB2_28) F1(IOB1_8)* F2(IOB1/GCLK0)* F3(IOB1_9)* F9(IOB2_31) F10(IOB2/GCLK2)* F11(IOB2_30) G1(IOB1_10)* G2(IOB1_11)* G10(IOB2_32) H1(IOB1_12)* H2(IOB1_13)* H3(IOB1_14)* H9(IOB2_35) H10(IOB2_33) J6(IOB1_15)* J10(IOB2_36) K3(IOB1_17)* K4(IOB1_18)* K5(IOB1_19)* K6(IOB1_20)* K7(IOB1_21)* K9(IOB1_22)* K10(IOB1_16)* K11(IOB2_38) L1(IOB1_23)* L2(IOB1_26)* L3(IOB1_27)* L4(IOB1_28)* L5(IOB1_29)* L6(IOB1_30)* L7(IOB1_31)* L8(IOB1/DEV_OE)* L9(IOB1_32)* L10(IOB1_24)* L11(IOB1_25)*; U38 4(VL_IO2)*; U49 26(IOB1_16)* 38(IOB1_25)*

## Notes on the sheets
sheet 17
- 10/100/1000 Ethernet
- RGMII Mode (default)
- Place near 88E1111 PHY
sheet 18
- HSMC Port A & Port B
- PLACE NEAR JTAG_TCK PIN NEAR HSMC PORT A
- PLACE NEAR JTAG_TCK PIN NEAR HSMC PORT B
- HSMC PORT A INTERFACE
- B
- A
- HSMC PORT B INTERFACE
- DDR ODT
sheet 19
- On-Board USB Blaster II
- ASSP JTAG INTERFACE
- USB INTERFACE
- MAX II USB INTERFACE
- JTAG INTERFACE
- PLACE NEAR CY7C68013A
- PLACE NEAR MAX II (U34)
sheet 20
- User I/O
- LED INTERFACE
- PUSH BUTTON INTERFACE
- DIP SWITCH INTERFACE
sheet 21
- ASSP CPLD
- MVE ASSP Core Interface
- DATA FLOWS FROM A to Y
- DATA FLOWS FROM A to Y
- PLACE NEAR MAX II EPM570
